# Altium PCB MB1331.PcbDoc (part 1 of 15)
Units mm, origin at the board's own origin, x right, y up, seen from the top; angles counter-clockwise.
Board outline 169.25 x 173.25 mm, 6 copper layers (Top Layer, Signal Layer 1, Signal Layer 2, Signal Layer 3, Signal Layer 4, Bottom Layer), stack 1.556 mm thick; 871 components, 699 nets, 3244 pads, 2370 vias.
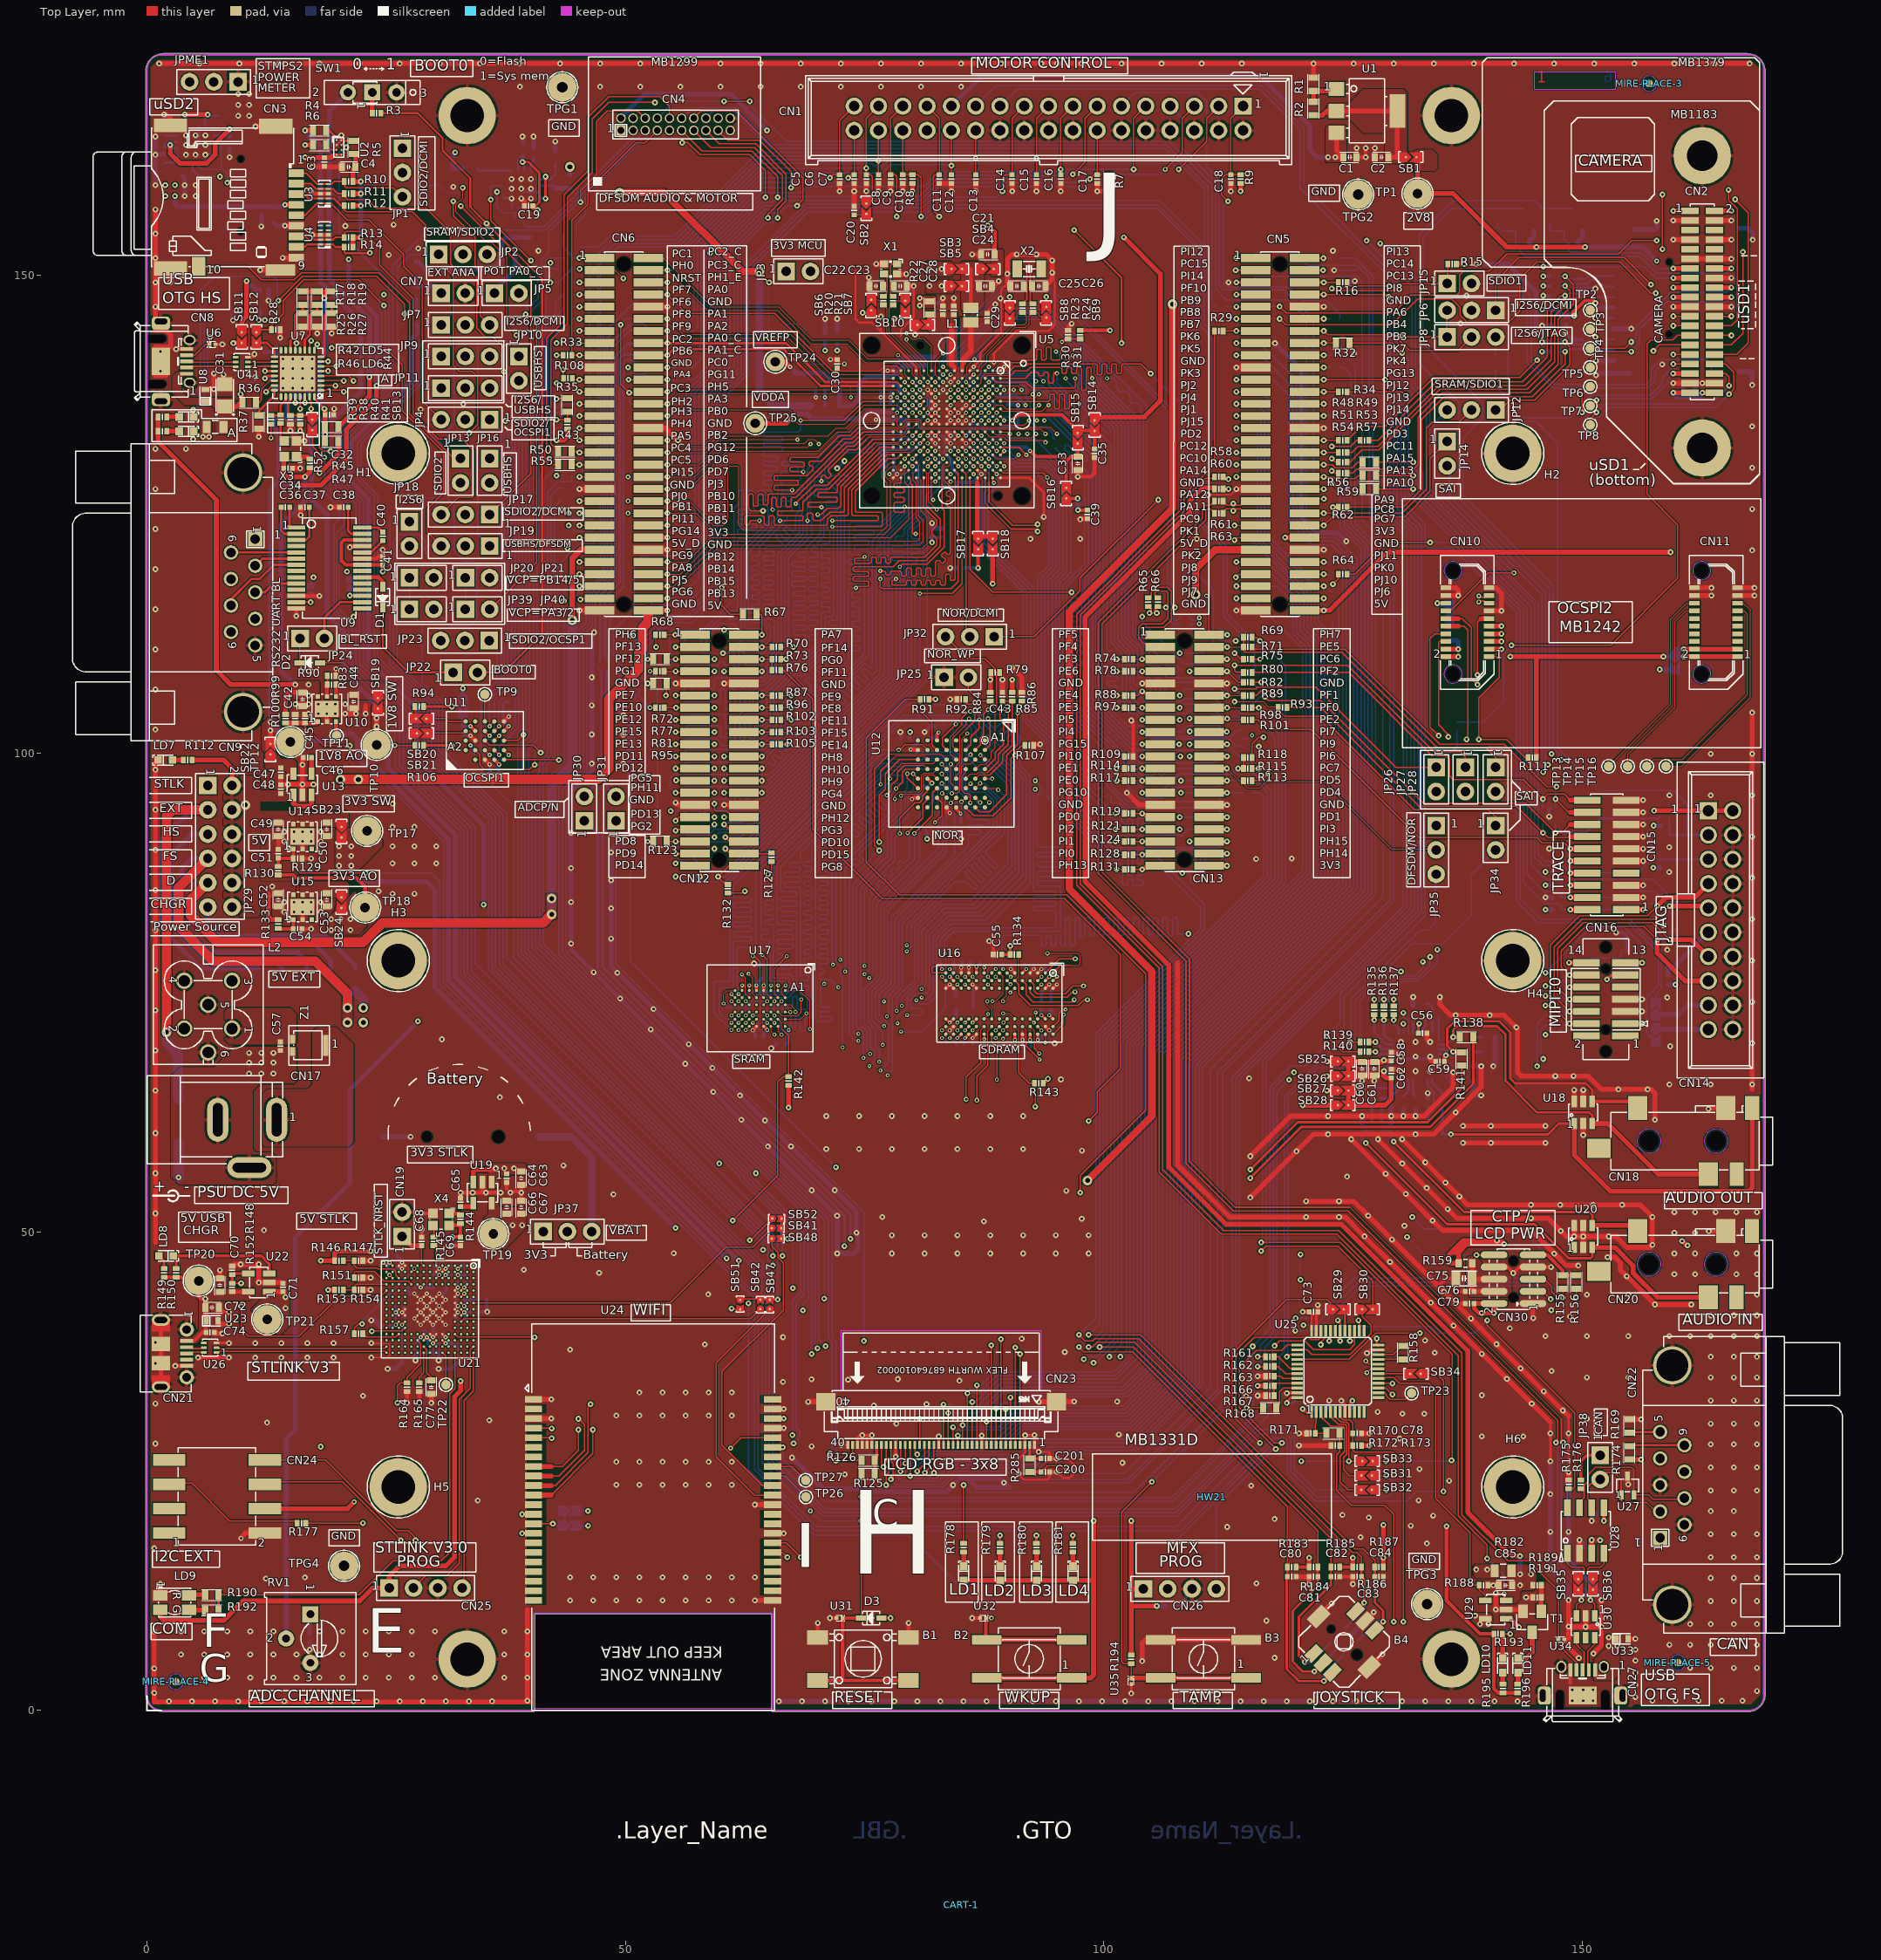
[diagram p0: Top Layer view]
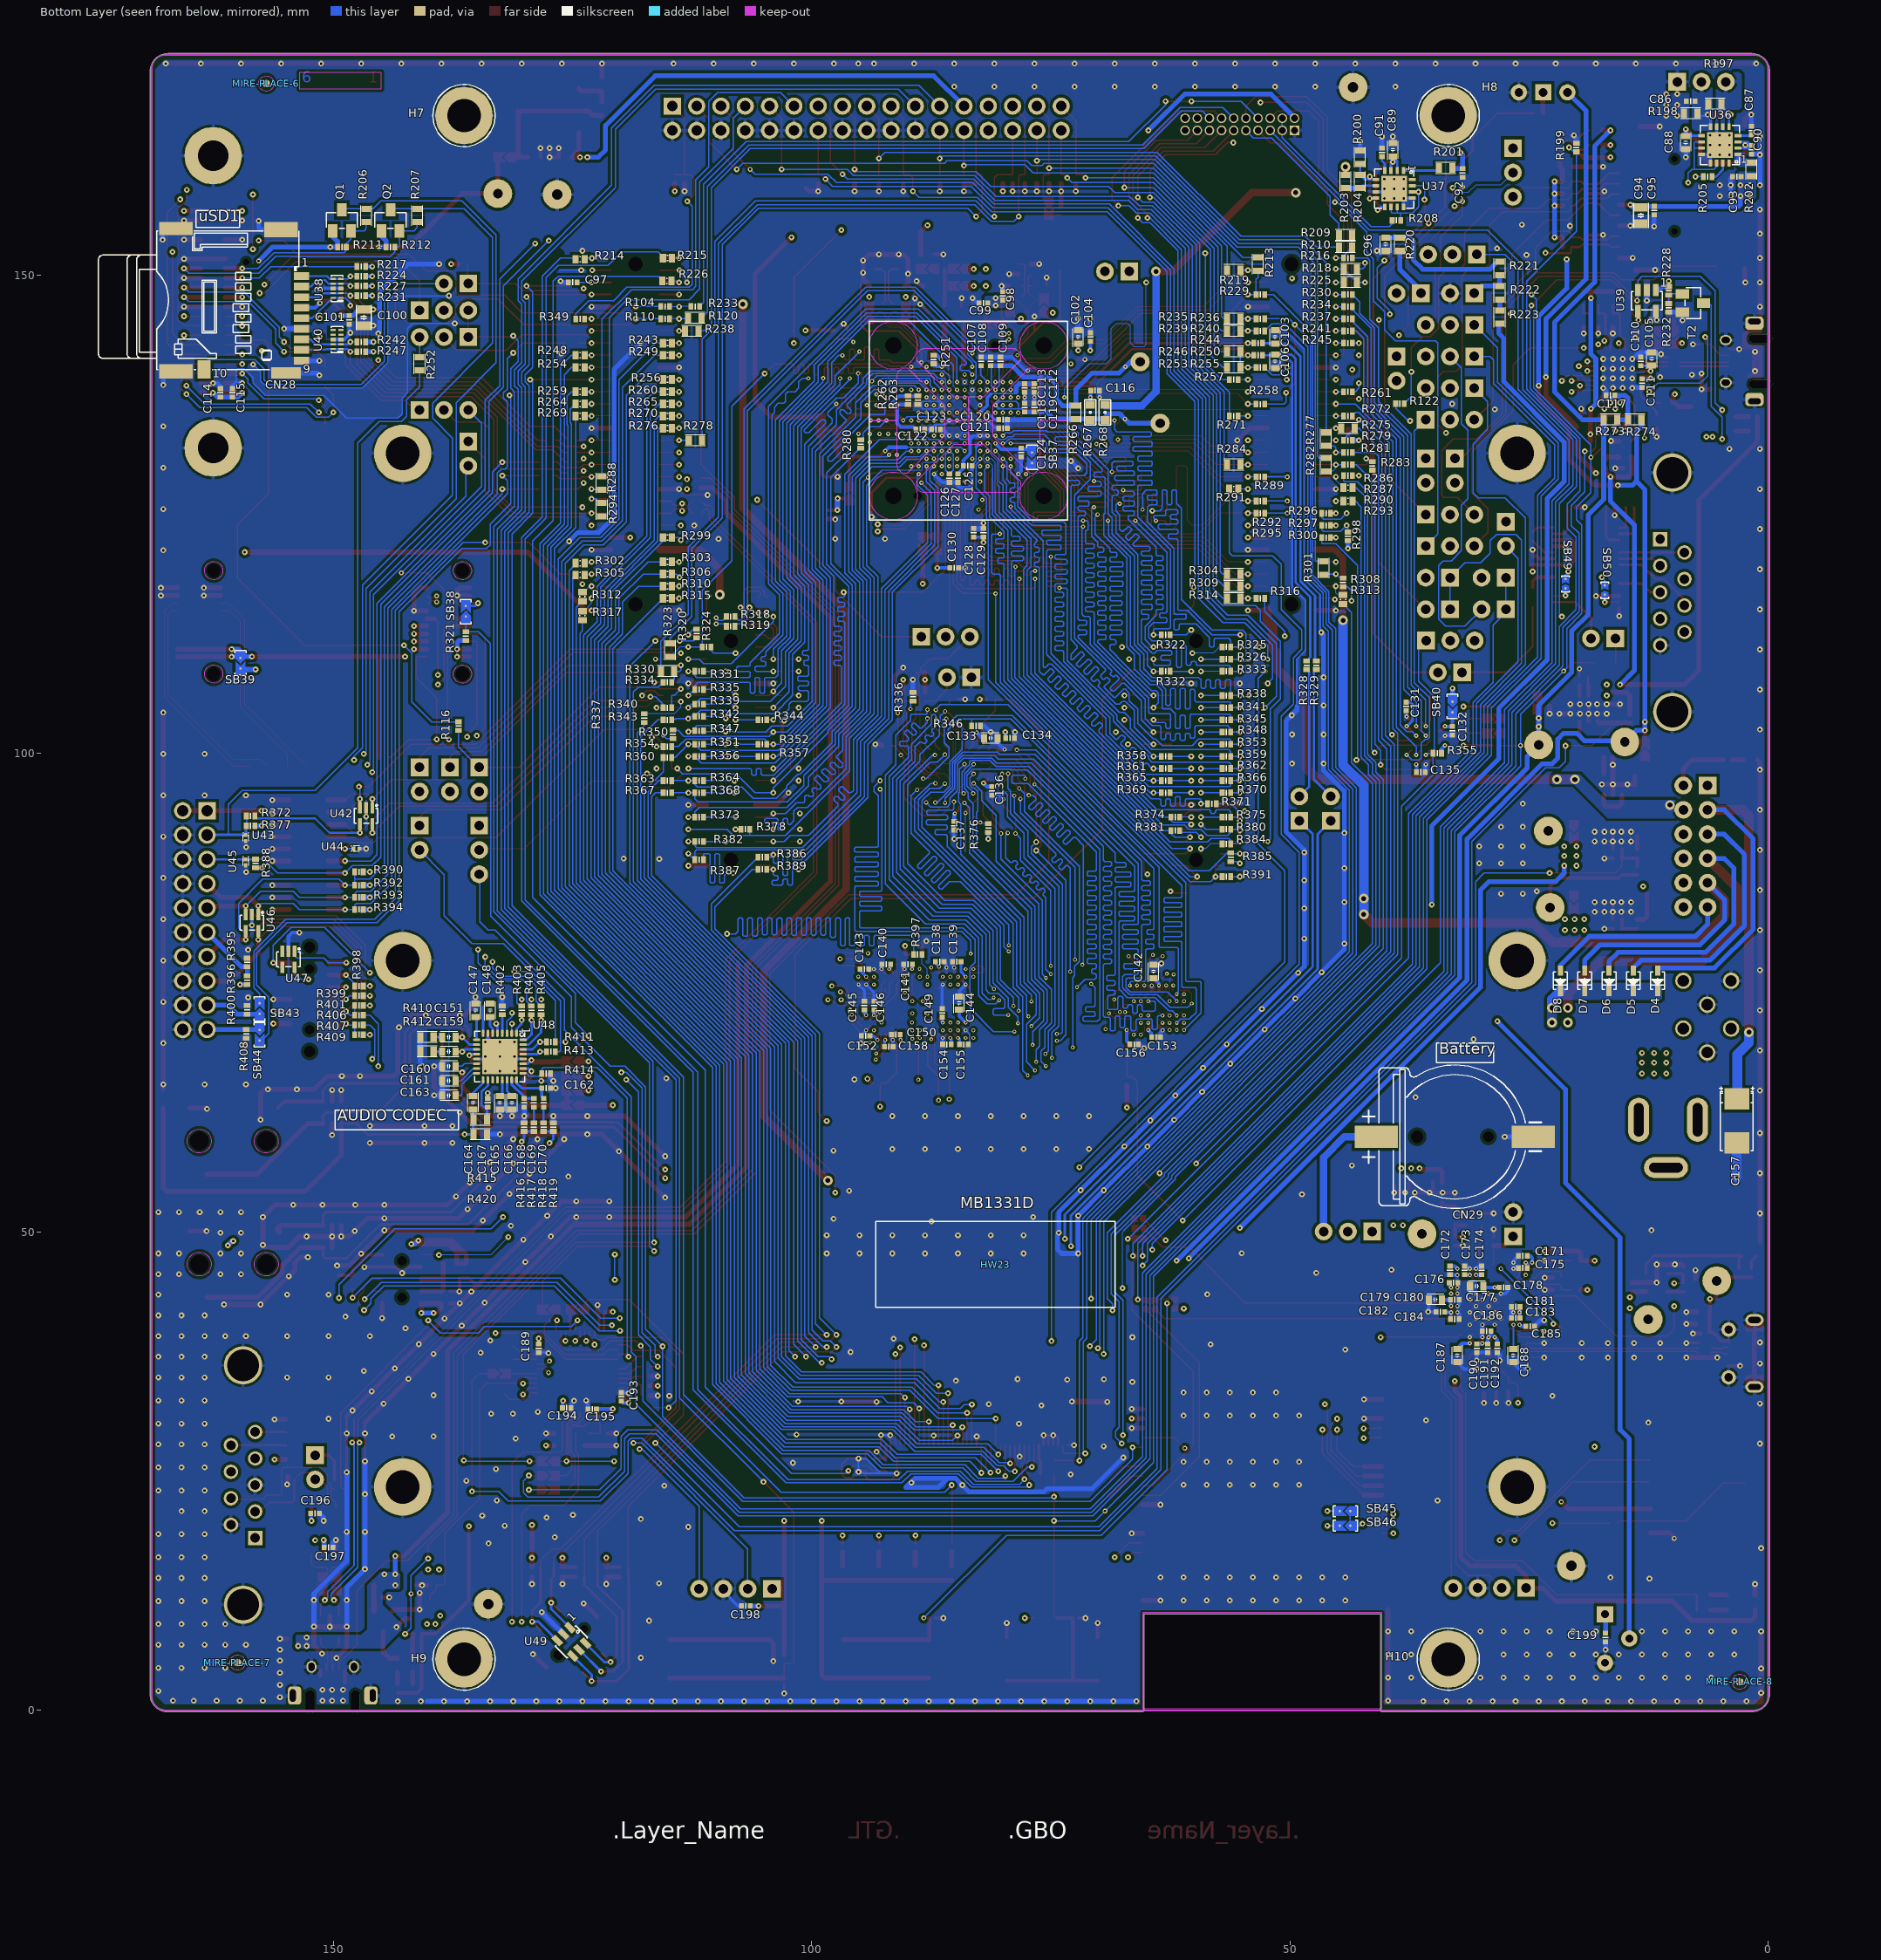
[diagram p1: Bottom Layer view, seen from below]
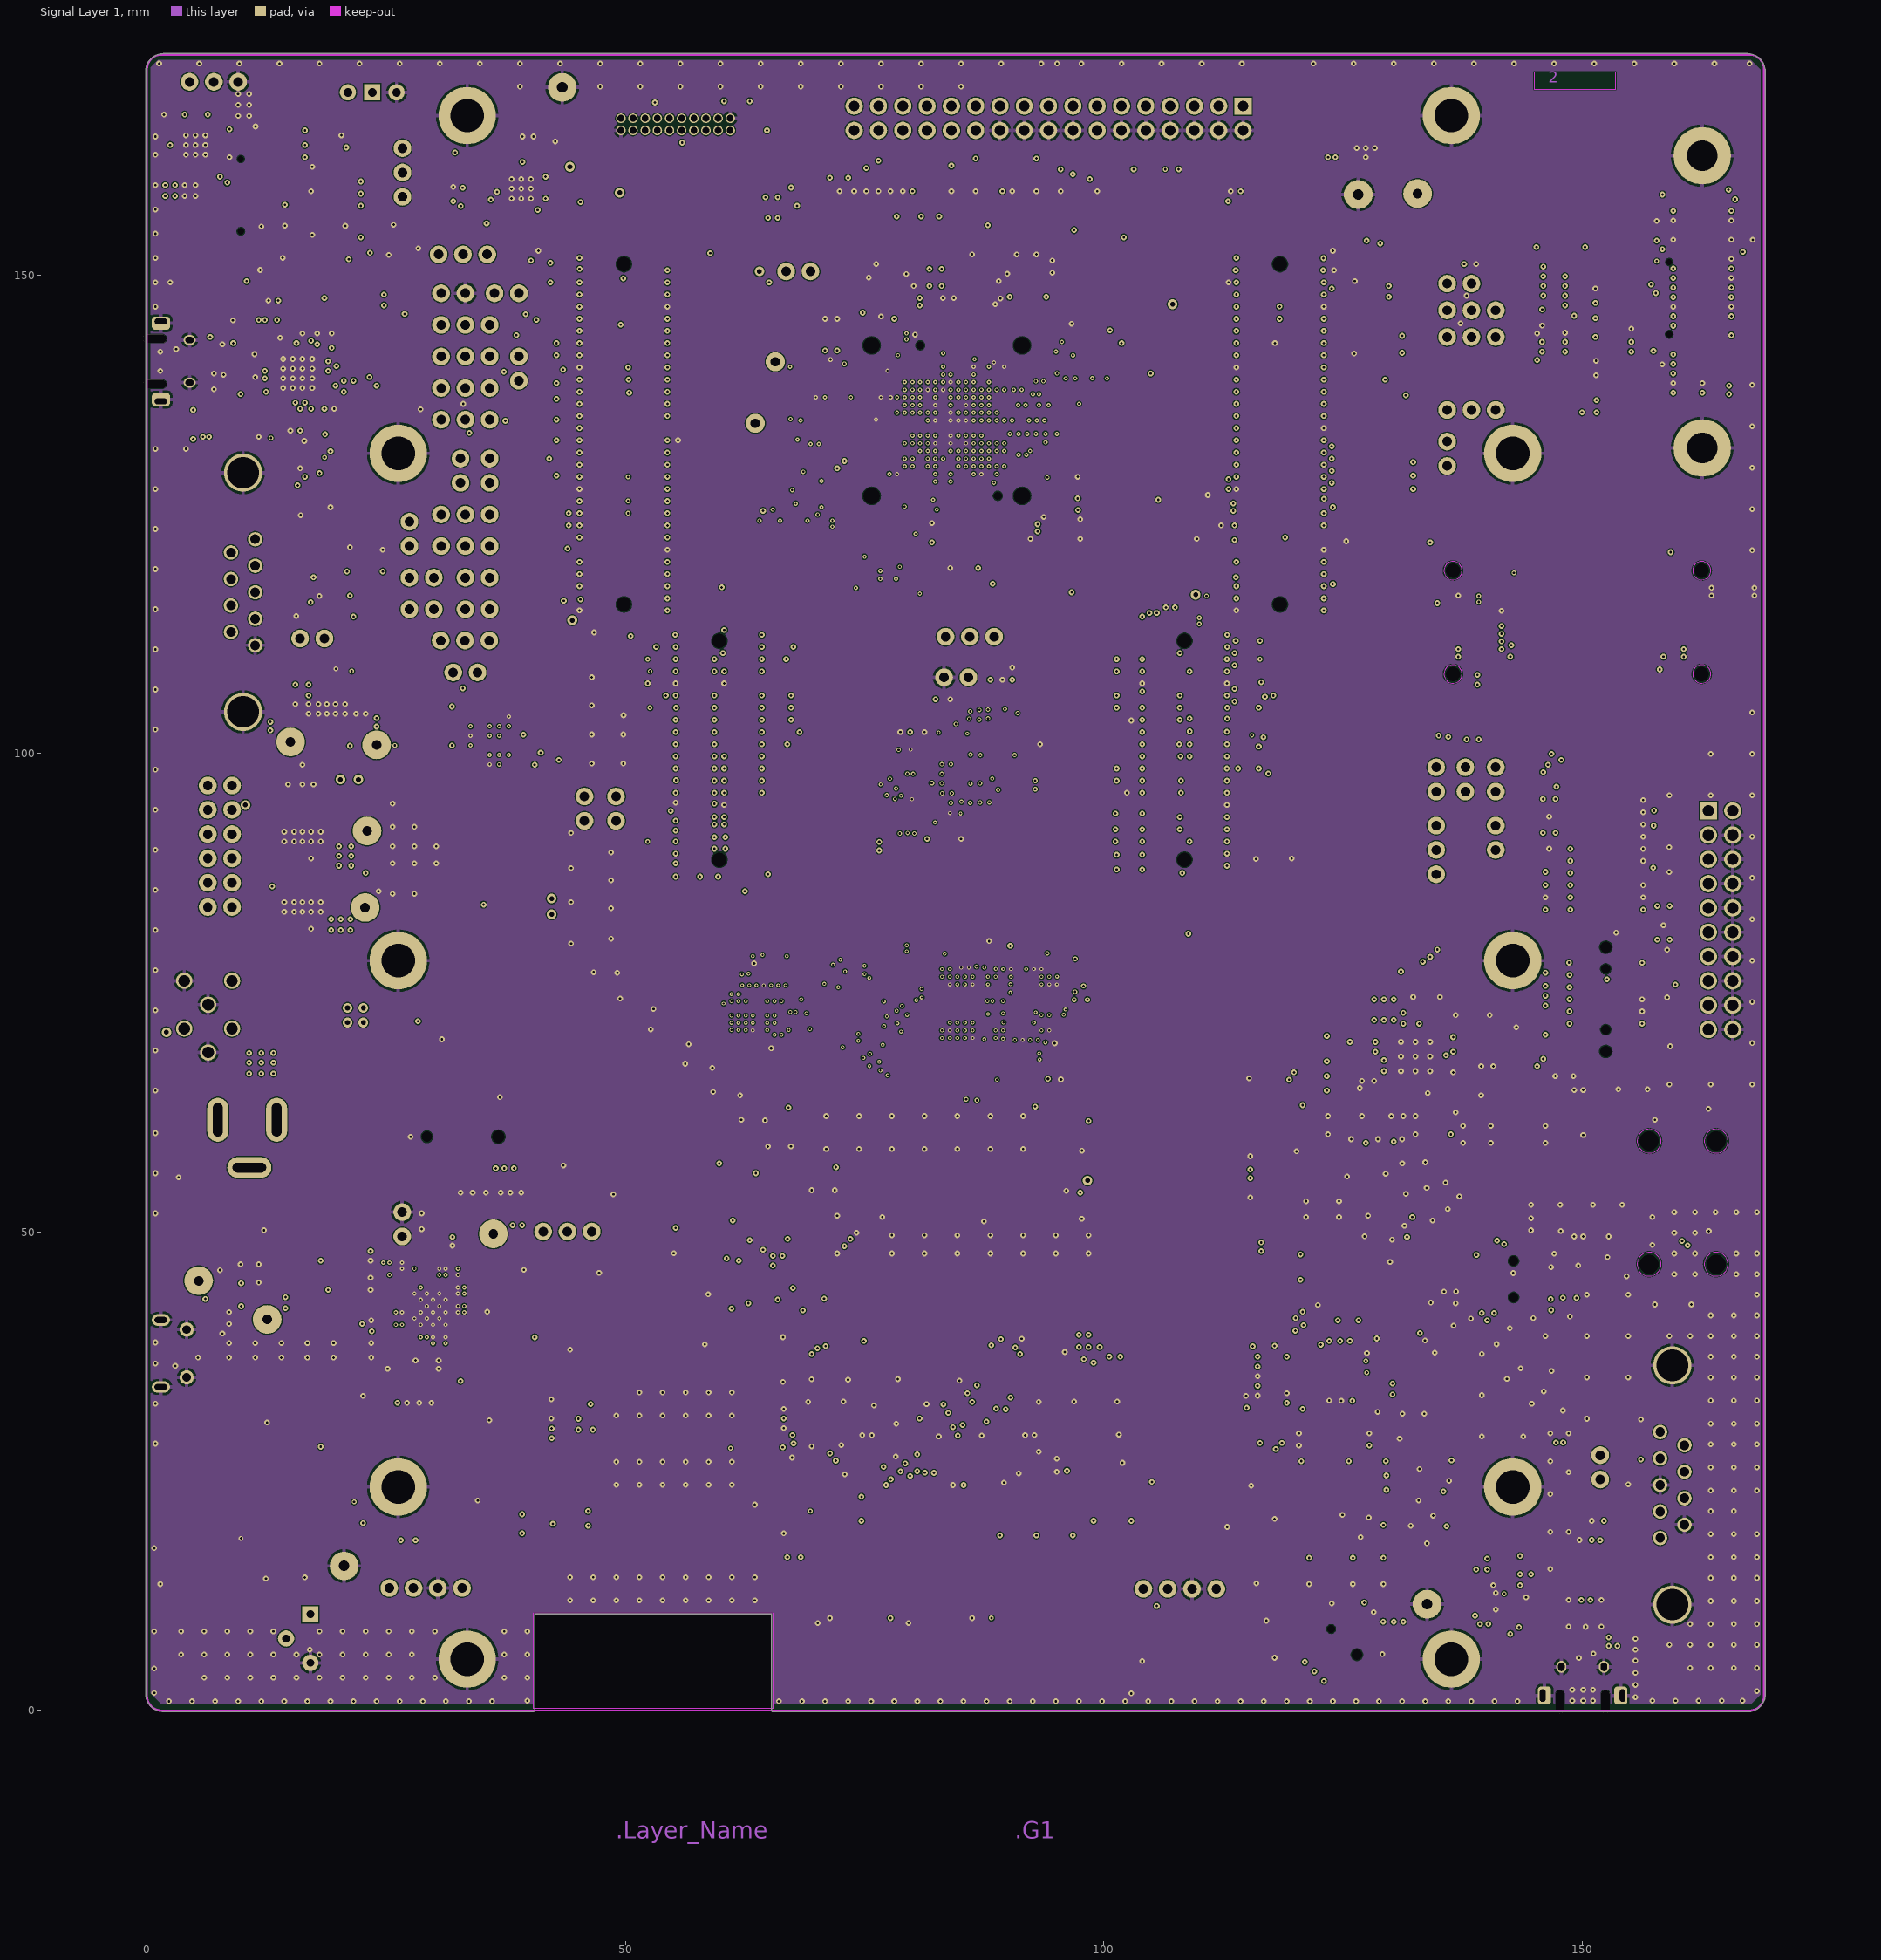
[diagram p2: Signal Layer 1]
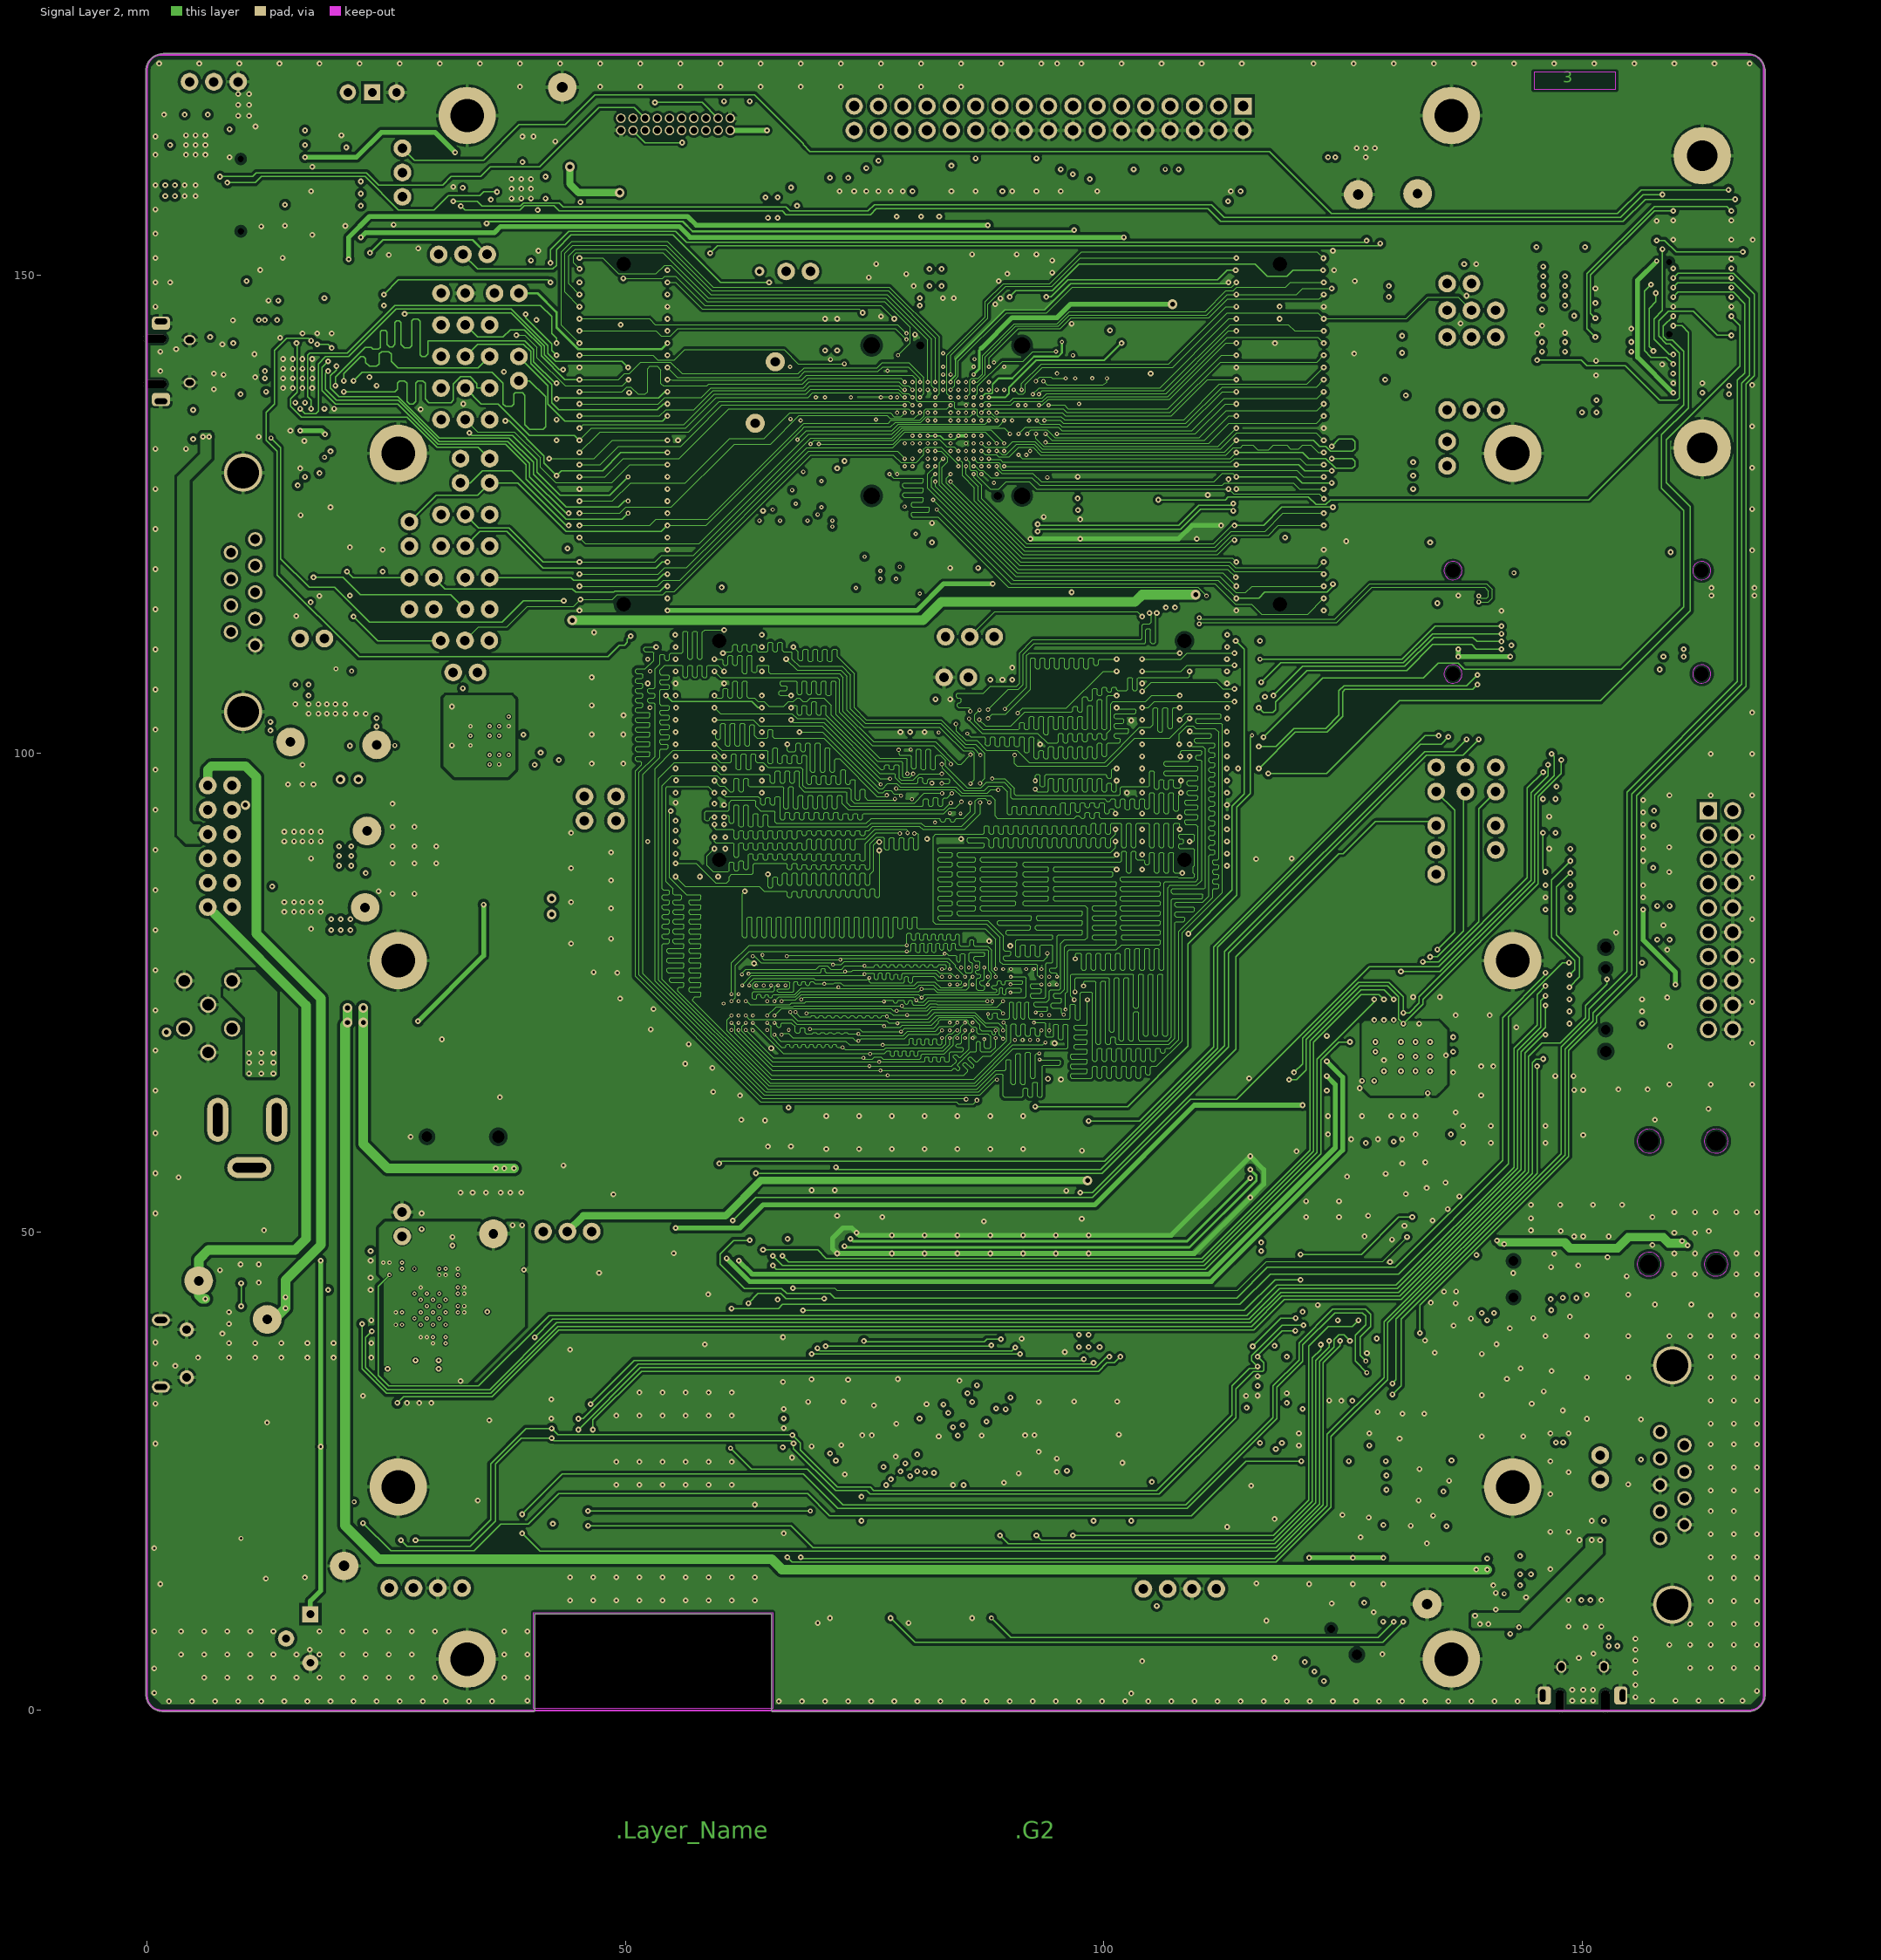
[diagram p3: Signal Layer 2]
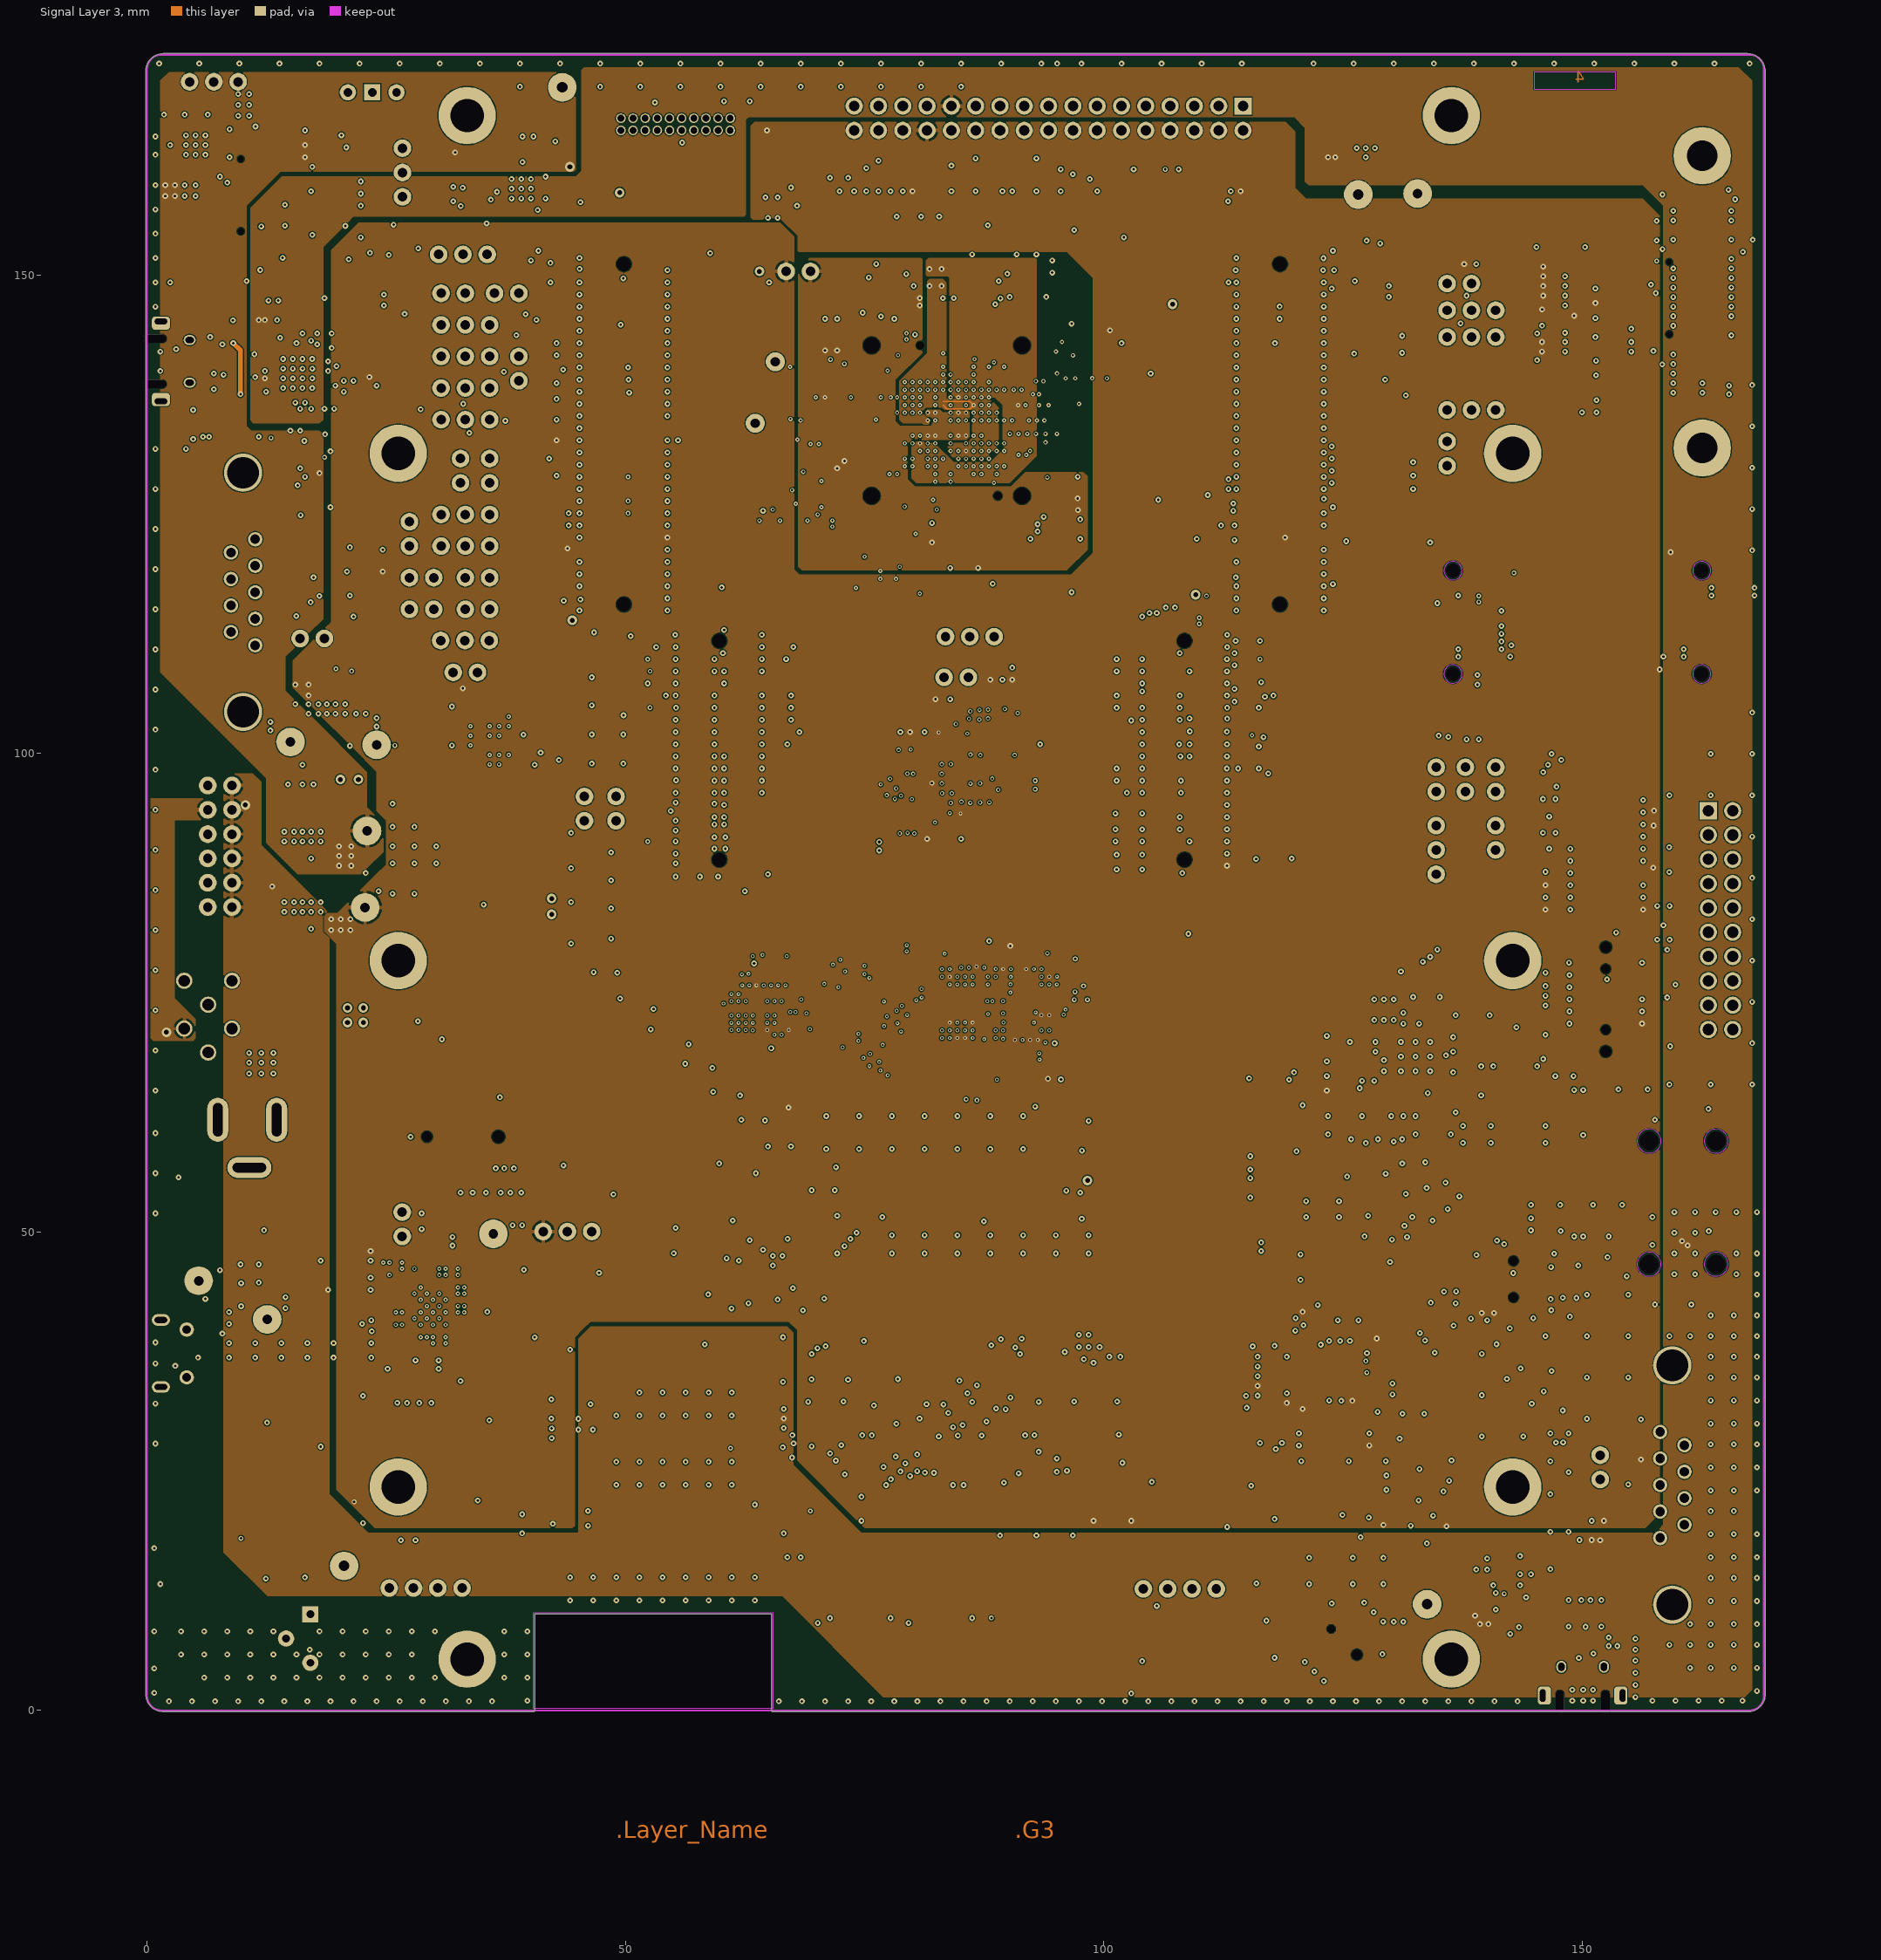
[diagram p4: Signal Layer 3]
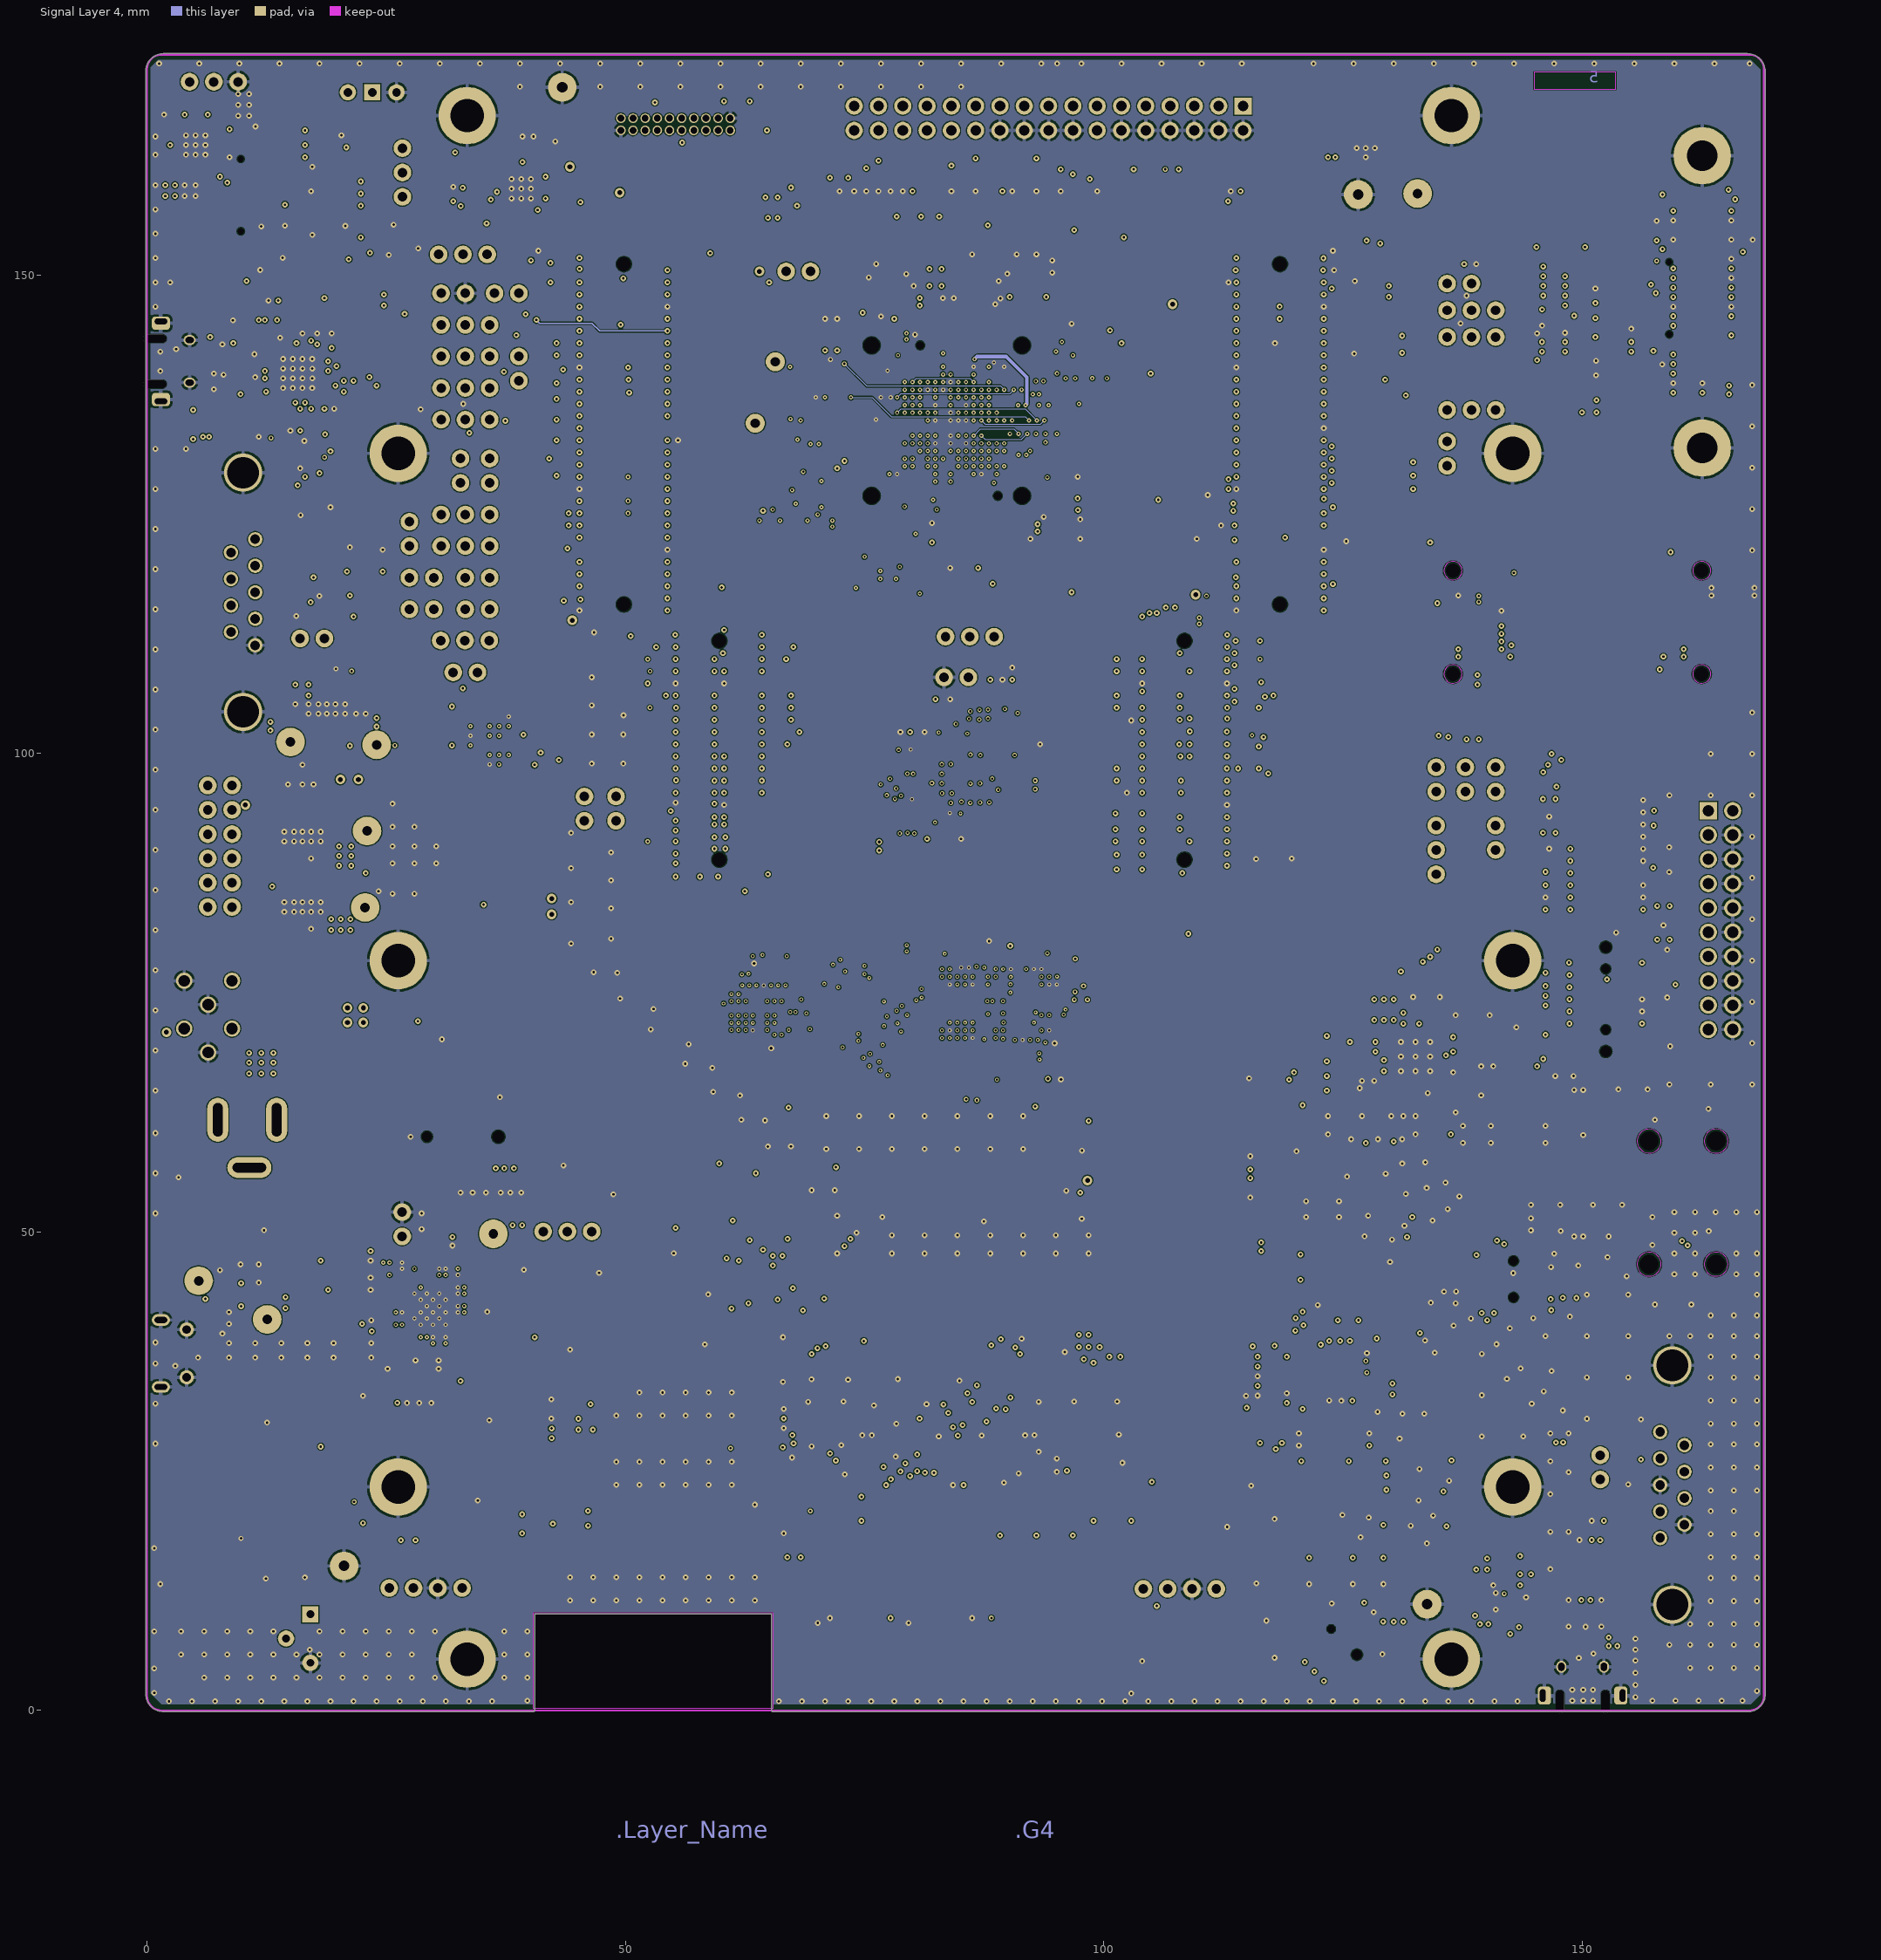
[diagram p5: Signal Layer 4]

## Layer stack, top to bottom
Top Solder: solder mask 0.0203, Solder Resist, Dk 3.5
Top Layer: signal copper 0.037
Dielectric 1: prepreg 0.0986, IT-180A 3313H, Dk 4.2
Signal Layer 1: signal copper 0.035
Dielectric 2: core 0.13, IT-180A, Dk 4.2
Signal Layer 2: signal copper 0.035
Dielectric 3: core 0.885, IT-180A 1080*2, Dk 4.25
Signal Layer 3: signal copper 0.035
Dielectric 4: core 0.13, IT-180A, Dk 4.2
Signal Layer 4: signal copper 0.035
Dielectric 5: prepreg 0.0986, IT-180A 3313H, Dk 4.2
Bottom Layer: signal copper 0.037
Bottom Solder: solder mask 0.0203, Solder Resist, Dk 3.5

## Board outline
-0.127,1.691 ccw(c1.725,1.725) 1.725,-0.127 ccw(c1.725,0) 1.725,-0.127 40.4,-0.117 ccw(c40.4,0.01) 40.527,0.01 40.527,10.073 65.273,10.073 65.273,0.01 ccw(c65.4,0.01) 65.4,-0.117 167.333,-0.127 ccw(c167.333,0) 167.333,-0.127 ccw(c167.333,1.667) 169.127,1.667 169.127,171.275 ccw(c167.275,171.275) 167.275,173.127 ccw(c167.275,173) 167.258,173.126 ccw(c167.24,173) 167.24,173.127 1.715,173.127 ccw(c1.715,173) 1.711,173.127 cw(c1.725,171.275) 1.725,173.127 1.711,173.127 ccw(c1.725,171.275) -0.127,171.275 ccw(c0,171.275) -0.127,171.262 ccw(c0,171.25) -0.127,171.25 -0.127,1.7 ccw(c0,1.7)

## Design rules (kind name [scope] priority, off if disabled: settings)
Clearance Clearance_4 [InNamedPolygon('GND_L03_P1184')] p1: gap=0.3 ignorepadtopadclearanceinfootprint=FALSE
Clearance Clearance_3 [InNamedPolygon('GND_L06_P1186')] p2: gap=0.3 ignorepadtopadclearanceinfootprint=FALSE
Clearance Clearance_2 [InNamedPolygon('GND_L01_P1178')] p3: gap=0.3 ignorepadtopadclearanceinfootprint=FALSE
Clearance Clearance_1 [All] p4 off: gap=0.1 ignorepadtopadclearanceinfootprint=TRUE except(0.15: Arc-Fill Track-Fill SMDPad-Fill THPad-Fill Via-Fill Fill-Fill; 0.2: Arc-THPad Track-THPad SMDPad-SMDPad SMDPad-THPad THPad-THPad; 0.3: Arc-Poly Track-Poly SMDPad-Poly THPad-Poly Via-Poly Poly-Poly)
Clearance [All] p5: gap=0.1 ignorepadtopadclearanceinfootprint=TRUE except(0.15: Arc-Fill Track-Fill SMDPad-Fill THPad-Fill Via-Fill Fill-Fill; 0.2: Arc-THPad Track-THPad SMDPad-SMDPad SMDPad-THPad THPad-THPad)
ComponentClearance [All] p1 off: gap=0.025 collisioncheckmode=3 verticalgap=0 showdistances=FALSE
DiffPairsRouting DiffPairsRouting_ADC_DIFF [InDifferentialPair('ADC_IN')   Or InDifferentialPair('ADC_JP_IN')    Or InDifferentialPair('ADC_JP_OUT')] p1: maxlimit=0.15 minlimit=0.15 mostfreqgap=0.15 toplayer_minwidth=0.254 toplayer_maxwidth=0.254 toplayer_prefwidth=0.254 midlayer1_minwidth=0.254 midlayer1_maxwidth=0.254 midlayer1_prefwidth=0.254 midlayer2_minwidth=0.254 midlayer2_maxwidth=0.254 midlayer2_prefwidth=0.254 midlayer3_minwidth=0.254 midlayer3_maxwidth=0.254 midlayer3_prefwidth=0.254 midlayer4_minwidth=0.254 midlayer4_maxwidth=0.254 midlayer4_prefwidth=0.254 bottomlayer_minwidth=0.254 bottomlayer_maxwidth=0.254 bottomlayer_prefwidth=0.254 maxuncoupledlength=12.7
DiffPairsRouting DiffPairsRouting_100 [InDifferentialPairClass('Diff_100')] p2: maxlimit=0.277 minlimit=0.251 mostfreqgap=0.277 toplayer_maxgap=0.251 toplayer_prefgap=0.251 toplayer_minwidth=0.13 toplayer_maxwidth=0.13 toplayer_prefwidth=0.13 midlayer1_mingap=0.277 midlayer1_minwidth=0.381 midlayer1_maxwidth=0.381 midlayer1_prefwidth=0.381 midlayer2_mingap=0.277 midlayer2_minwidth=0.104 midlayer2_maxwidth=0.104 midlayer2_prefwidth=0.104 midlayer3_mingap=0.277 midlayer3_minwidth=0.381 midlayer3_maxwidth=0.381 midlayer3_prefwidth=0.381 midlayer4_mingap=0.277 midlayer4_minwidth=0.381 midlayer4_maxwidth=0.381 midlayer4_prefwidth=0.381 bottomlayer_maxgap=0.251 bottomlayer_prefgap=0.251 bottomlayer_minwidth=0.13 bottomlayer_maxwidth=0.13 bottomlayer_prefwidth=0.13 maxuncoupledlength=12.7
DiffPairsRouting DiffPairsRouting_90 [InDifferentialPairClass('Diff_90')] p3: maxlimit=0.251 minlimit=0.226 mostfreqgap=0.251 toplayer_maxgap=0.226 toplayer_prefgap=0.226 toplayer_minwidth=0.155 toplayer_maxwidth=0.155 toplayer_prefwidth=0.155 midlayer1_mingap=0.251 midlayer1_minwidth=0.381 midlayer1_maxwidth=0.381 midlayer1_prefwidth=0.381 midlayer2_mingap=0.251 midlayer2_minwidth=0.13 midlayer2_maxwidth=0.13 midlayer2_prefwidth=0.13 midlayer3_mingap=0.251 midlayer3_minwidth=0.381 midlayer3_maxwidth=0.381 midlayer3_prefwidth=0.381 midlayer4_mingap=0.251 midlayer4_minwidth=0.381 midlayer4_maxwidth=0.381 midlayer4_prefwidth=0.381 bottomlayer_maxgap=0.226 bottomlayer_prefgap=0.226 bottomlayer_minwidth=0.155 bottomlayer_maxwidth=0.155 bottomlayer_prefwidth=0.155 maxuncoupledlength=12.7
FabricationTestpoint [(IsPad And (OnTopLayer Or OnBottomLayer))] p1: side=3 testpointundercomponent=TRUE minsize=1.016 maxsize=2.54 preferedsize=1.524 minholesize=0 maxholesize=1.016 preferedholesize=0.813 testpointgrid=0.025 allowsidetop=TRUE allowsidebottom=TRUE usegrid=TRUE gridtolerance=0
HoleSize [All] p1: absolutevalues=TRUE maxlimit=25.375 minlimit=0.025 maxpercent=80.000 minpercent=20.000
MatchedLengths MatchedLengths_SDIO1_MCU [InNetClass('SDIO1_MCU')] p1: tolerance=7 checknetsindiffpair=FALSE checkdiffpairvsdiffpair=TRUE checkxsignals=TRUE checkothers=TRUE
MatchedLengths MatchedLengths_SDIO2_MCU [InNetClass('SDIO2_MCU')] p2: tolerance=7 checknetsindiffpair=FALSE checkdiffpairvsdiffpair=TRUE checkxsignals=TRUE checkothers=TRUE
MatchedLengths MatchedLengths_ULPI_MCU [InNetClass('ULPI_MCU')] p3: tolerance=17 checknetsindiffpair=FALSE checkdiffpairvsdiffpair=TRUE checkxsignals=TRUE checkothers=TRUE
MatchedLengths MatchedLengths_CAMERA_MCU [InNetClass('CAMERA_MCU')] p4: tolerance=17 checknetsindiffpair=FALSE checkdiffpairvsdiffpair=TRUE checkxsignals=TRUE checkothers=TRUE
MatchedLengths MatchedLengths_FMC_DATA_MCU [InNetClass('FMC DATA_MCU')] p5: tolerance=3 checknetsindiffpair=FALSE checkdiffpairvsdiffpair=TRUE checkxsignals=TRUE checkothers=TRUE
MatchedLengths MatchedLengths_FMC_ADR_CMD_MCU [InNetClass('FMC ADR+CMD_MCU')] p6: tolerance=3 checknetsindiffpair=FALSE checkdiffpairvsdiffpair=TRUE checkxsignals=TRUE checkothers=TRUE
MatchedLengths MatchedLengths_SDIO1 [InNetClass('SDIO1')] p7: tolerance=7 checknetsindiffpair=FALSE checkdiffpairvsdiffpair=TRUE checkxsignals=TRUE checkothers=TRUE
MatchedLengths MatchedLengths_SDIO2 [InNetClass('SDIO2')] p8: tolerance=7 checknetsindiffpair=FALSE checkdiffpairvsdiffpair=TRUE checkxsignals=TRUE checkothers=TRUE
MatchedLengths MatchedLengths_ULPI [InNetClass('ULPI')] p9: tolerance=17 checknetsindiffpair=FALSE checkdiffpairvsdiffpair=TRUE checkxsignals=TRUE checkothers=TRUE
MatchedLengths MatchedLengths_CAMERA [InNetClass('CAMERA')] p10: tolerance=17 checknetsindiffpair=FALSE checkdiffpairvsdiffpair=TRUE checkxsignals=TRUE checkothers=TRUE
MatchedLengths MatchedLengths_FMC_DATA [InNetClass('FMC DATA')] p11: tolerance=3 checknetsindiffpair=FALSE checkdiffpairvsdiffpair=TRUE checkxsignals=TRUE checkothers=TRUE
MatchedLengths MatchedLengths_FMC_ADR_CMD [InNetClass('FMC ADR+CMD')] p12: tolerance=3 checknetsindiffpair=FALSE checkdiffpairvsdiffpair=TRUE checkxsignals=TRUE checkothers=TRUE
MaxMinImpedance "Schematic Impedance Constraint" [InNet('USB_DEV_HS_P')] p1: minimum=85,00 maximum=95,00
MaxMinImpedance "Schematic Impedance Constraint_6" [InNet('USB_DEV_HS_N')] p2: minimum=85,00 maximum=95,00
MaxMinImpedance "Schematic Impedance Constraint_3" [InNet('USB_DEV_HS_CN_P')] p3: minimum=85,00 maximum=95,00
MaxMinImpedance "Schematic Impedance Constraint_2" [InNet('USB_DEV_HS_CN_N')] p4: minimum=85,00 maximum=95,00
MinimumSolderMaskSliver [All] p1: minsoldermaskwidth=0
PlaneClearance [All] p1: clearance=0.6
PlaneConnect [All] p1: planeconnectstyle=Direct reliefexpansion=0.508 reliefentries=4 reliefconductorwidth=0.4 reliefairgap=0.4
PolygonConnect PolygonConnect_via [IsVia] p1: connectstyle=Direct reliefconductorwidth=0.254 reliefentries=4 polygonreliefangle="90 Angle" airgapwidth=0.254
PolygonConnect [All] p2: thpad.connectstyle=Relief thpad.reliefconductorwidth=0.4 thpad.reliefentries=4 thpad.polygonreliefangle="90 Angle" thpad.airgapwidth=0.25 smdpad.connectstyle=Direct smdpad.reliefconductorwidth=0.4 smdpad.reliefentries=4 smdpad.polygonreliefangle="90 Angle" smdpad.airgapwidth=0.254 via.connectstyle=Direct via.reliefconductorwidth=0.4 via.reliefentries=4 via.polygonreliefangle="90 Angle" via.airgapwidth=0.254
RoutingPriority RoutingPriority_ALL [All] p1: routingpriority=1
RoutingVias [All] p1: holewidth=0.254 width=0.6 viastyle="Through Hole" minholewidth=0.254 minwidth=0.6 maxholewidth=0.254 maxwidth=0.6
SilkToSilkClearance [All] p1: silktosilkclearance=0
SilkToSolderMaskClearance [IsPad] p1: minsilkscreentomaskgap=0 clearancetoexposedcopper=TRUE
SolderMaskExpansion [All] p1: expansion=0.05
Width Width_POWER [InNetClass('Power')] p1: maxlimit=2 minlimit=0.1 preferedwidth=0.4 minimp=50.000000 maximp=50.000000 favimp=50.000000
Width [All] p2: maxlimit=253.975 minlimit=0.1 preferedwidth=0.1
20 further rules are at their usual default settings.

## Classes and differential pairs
net class "UART VCP": J_RX J_TX PA2 PA3 PB14 PB15 RS232_USART_RX RS232_USART_TX STLK_VCP_RX STLK_VCP_TX T_VCP_RX T_VCP_TX WIFI_UART_RX WIFI_UART_TX
differential pair class ADC_DIFF: ADC_IN ADC_JP_IN ADC_JP_OUT
net class "USB FS_MCU": PA11 PA12
net class ULPI: ULPI_D0 ULPI_D1 ULPI_D2 ULPI_D3 ULPI_D4 ULPI_D5 ULPI_D6 ULPI_D7
net class SDIO2_MCU: PG0 PG1 PG2 PG3 PG4 PG5 PG6 PG7 PG8 PG9 PG10 PG11 PG12 PG13 PG14 PG15
net class SDIO1_MCU: PC0 PC1 PC2 PC3 PC4 PC5 PC6 PC7 PC8 PC9 PC10 PC11 PC12 PC13 PC14 PC15
net class "SDR DATA": D0 D1 D2 D3 D4 D5 D6 D7 D8 D9 D10 D11 D12 D13 D14 D15 D16 D17 D18 D19 D20 D21 D22 D23 D24 D25 D26 D27 D28 D29 D30 D31
net class "SDR ADR+CMD": A0 A1 A2 A3 A4 A5 A6 A7 A8 A9 A10 A11 A12 A13 A14 A15 A16 A17 A18 A19 A20 A21 A22 A23
net class CAMERA: DCMI_D0 DCMI_D1 DCMI_D2 DCMI_D3 DCMI_D4 DCMI_D5 DCMI_D6 DCMI_D7
net class SDIO2: SDIO2_CK SDIO2_CMD SDIO2_D0 SDIO2_D1 SDIO2_D2 SDIO2_D3
net class SDIO1: SDIO1_CK SDIO1_CMD SDIO1_D0 SDIO1_D1 SDIO1_D2 SDIO1_D3
net class "USB HS USER": USB_HS_N USB_HS_P
net class "USB FS": USB_OTG_FS_N USB_OTG_FS_P
net class "USB HS STLINK": USB_DEV_HS_CN_N USB_DEV_HS_CN_P USB_DEV_HS_N USB_DEV_HS_P
differential pair class Diff_90: USB_DEV_HS USB_DEV_HS_CN USB_HS USB_OTG_FS
differential pair class Diff_100: OCSPI2_CLK
net class ULPI_MCU: PB0 PB1 PB2 PB3 PB4 PB5 PB6 PB7 PB8 PB9 PB10 PB11 PB12 PB13 PB14 PB15
net class CAMERA_MCU: PH0 PH1 PH2 PH3 PH4 PH5 PH6 PH7 PH8 PH9 PH10 PH11 PH12 PH13 PH14 PH15
net class "SDR DATA_MCU": PE0 PE1 PE2 PE3 PE4 PE5 PE6 PE7 PE8 PE9 PE10 PE11 PE12 PE13 PE14 PE15
net class "SDR ADR+CMD_MCU": PF0 PF1 PF2 PF3 PF4 PF5 PF6 PF7 PF8 PF9 PF10 PF11 PF12 PF13 PF14 PF15
component class U_USB_OTG_HS_externalPHY: C31 C32 C34 C105 C110 C111 C117 CN8 LD5 LD6 R17 R18 R19 R25 R26 R27 R28 R36 R37 R38 R39 R40 R41 R42 R44 R45 R46 R47 R52 R228 R232 R273 R274 SB11 SB12 SB13 T2 U6 U7 U8 U39 U41 X3
component class U_USB_OTG_FS: C85 CN27 LD10 LD11 R182 R188 R189 R191 R193 R195 R196 T1 U29 U30 U33 U34
component class U_Top: H7 H8 H9 H10 HW8 HW9 HW10 HW11 HW12 HW13 HW14 HW15 HW16 HW17 HW18 HW19 HW20 HW21 HW22 HW23 HW24 HW25 HW26 SB29 SB30 SB31 SB32 SB33 SB34 TPG1 TPG2 TPG3 TPG4
component class U_STMPS2&PT100: C19 C86 C87 C88 C89 C90 C91 C92 C93 JPME1 R33 R197 R198 R200 R201 R202 R203 R204 R205 R208 U36 U37
component class U_STLink_V3E_SWD: C63 C64 C65 C66 C67 C68 C69 C70 C71 C72 C74 C77 C171 C172 C173 C174 C175 C176 C177 C178 C179 C180 C181 C182 C183 C184 C185 C186 C187 C188 C190 C191 C192 CN19 CN21 CN25 D4 D5 D6 D7 D8 LD8 LD9 R144 R145 R146 R147 R148 R149 R150 R151 R152 R153 R154 R157 R165 R190 R192 R398 R399 R401 R409 SB41 SB42 TP19 TP20 TP21 TP22 U19 U21 U22 U23 U26 X4
component class U_SDcard: C94 C95 C100 C101 CN3 CN28 HW46 HW47 JP13 JP15 R10 R11 R12 R13 R14 R15 R224 R227 R231 R242 R247 R298 U3 U4 U38 U40
component class U_Power_MCU: C21 C24 C27 C28 C29 C33 C35 C39 C98 C99 C102 C104 C108 C109 C112 C113 C116 C118 C119 C120 C121 C122 C123 C124 C125 C126 C127 C128 C129 C130 CN29 HW56 HW57 JP3 JP37 L1 R22 R251 R262 R263 R266 R267 R268 SB3 SB4 SB5 SB10 SB14 SB15 SB16 SB17 SB18 SB37 SB73 TP24 TP25
component class U_Power_Board: C1 C2 C42 C44 C45 C46 C47 C48 C49 C50 C51 C52 C53 C54 C57 C157 CN17 HW55 JP29 L2 LD7 R1 R2 R83 R90 R99 R100 R112 R129 R130 R133 SB1 SB19 SB22 SB23 SB24 TP1 TP10 TP11 TP12 TP17 TP18 U1 U10 U13 U14 U15 Z1
component class U_Peripherals: B2 B3 C96 C199 CN7 CN24 HW51 HW52 LD1 LD2 LD3 LD4 R172 R177 R178 R179 R180 R181 R194 R220 R221 R222 R223 R406 R407 RV1 SB45 SB46 TP26 TP27 U24 U32 U35
component class U_OCSPI: C131 C132 C135 CN10 CN11 HW45 R94 R106 R111 R321 R355 SB20 SB21 SB38 SB39 SB40 TP9 TP13 TP14 TP15 TP16 U11
component class U_MotorControl: B4 C5 C6 C7 C8 C9 C10 C11 C12 C13 C14 C15 C16 C17 C18 C20 C80 C81 C82 C83 C84 CN1 R7 R8 R9 R183 R184 R185 R186 R187 SB2 U49
component class U_MFX: C73 C78 C189 C193 C194 C195 C198 CN26 D3 R158 R161 R162 R163 R166 R167 R168 R170 R171 R173 TP23 U25
component class U_Memory: C43 C55 C133 C134 C136 C137 C138 C139 C140 C141 C142 C143 C144 C145 C146 C149 C150 C152 C153 C154 C155 C156 C158 JP25 R79 R84 R85 R86 R91 R92 R107 R109 R134 R142 R143 R336 R346 R376 R397 U12 U16 U17
component class U_MCU: 1.4 C30 C97 HW27 HW28 HW31 HW32 HW34 HW35 HW36 HW37 HW38 HW39 HW41 HW42 HW43 HW44 JP1 JP2 JP4 JP5 JP6 JP7 JP8 JP9 JP10 JP11 JP12 JP14 JP16 JP17 JP18 JP19 JP20 JP21 JP23 JP26 JP27 JP28 JP32 JP34 JP35 JP39 JP40 R16 R23 R24 R29 R34 R35 R43 R48 R49 R50 R51 R54 R55 R56 R58 R60 R61 R62 R63 R64 R65 R66 R67 R68 R69 R70 R71 R72 R73 R74 R75 R76 R77 R78 R80 R81 R82 R87 R88 R89 R93 R95 R96 R97 R98 R101 R102 R103 R104 R105 R108 R110 R113 R114 R115 R116 R117 R118 R119 R120 R121 R122 R123 R124 R127 R128 R131 R132 R209 R210 R213 R214 R215 R216 R219 R226 R229 R230 R233 R234 R235 R236 R237 R238 R239 R240 R241 R243 R244 R245 R246 R248 R249 R250 R253 R254 R255 R256 R257 R258 R259 R260 R261 R264 R265 R269 R270 R271 R272 R275 R276 R277 R278 R279 R280 R281 R282 R283 R284 R286 R287 R288 R289 R290 R291 R292 R293 R294 R295 R296 R297 R299 R300 R301 R302 R303 R304 R305 R306 R308 R309 R310 R312 R313 R314 R315 R316 R317 R318 R319 R320 R322 R323 R324 R325 R326 R330 R331 R332 R333 R334 R335 R337 R338 R339 R340 R341 R342 R343 R344 R345 R347 R348 R349 R350 R351 R352 R353 R354 R356 R357 R358 R359 R360 R361 R362 R363 R364 R365 R366 R367 R368 R369 R370 R371 R373 R374 R375 R378 R380 R381 R382 R384 R385 R386 R387 R389 R391 SB35 SB36 SB47 SB48 SB49 SB50 U5
component class U_MCU_Clock&Reset: B1 C22 C23 C25 C26 C107 D1 D2 JP22 JP24 R3 R20 R21 R30 R31 SW1 U31 X1 X2
component class U_LCD: C75 C76 C79 H1 H2 H3 H4 H5 H6 R159
component class U_JTAG&Trace: CN14 CN15 CN16 R32 R53 R57 R59 R164 R218 R252 R372 R377 R388 R390 R392 R393 R394 R395 R396 R400 R408 SB43 SB44 SB51 SB52 U42 U43 U44 U45 U46 U47
component class U_FDCAN&RS232: C36 C37 C38 C40 C41 C196 C197 CN9 CN22 HW53 HW54 JP38 R169 R174 R175 R176 U9 U27 U28
component class U_ExtensionConnector: CN5 CN6 CN12 CN13 R225 SB6 SB7 SB8 SB9
component class U_Camera: C114 C115 CN2 Q1 Q2 R206 R207 R211 R212 R217 TP2 TP3 TP4 TP5 TP6 TP7 TP8
component class U_DFSDM_Audio&Motor: CN4 HW48
component class U_Audio_Codec: C56 C58 C59 C60 C61 C62 C103 C106 C147 C148 C151 C159 C160 C161 C162 C163 C164 C165 C166 C167 C168 C169 C170 CN18 CN20 JP30 JP31 R135 R136 R137 R138 R139 R140 R141 R328 R329 R402 R403 R404 R405 R410 R411 R412 R413 R414 R415 R416 R417 R418 R419 R420 SB25 SB26 SB27 SB28 U18 U20 U48
net class Power: 1V8_AO 1V8_CODEC 1V8_LDO 1V8_SW 1V8_USBHS 2V8 3V3_AO 3V3_CODEC 3V3_MCU 3V3_OCSPI1 3V3_OCSPI2 3V3_SMPS_IN 3V3_STLK 3V3_SW 3V3_USBHS_IO 3V3_VBAT 3V3_VDDA 3V3_VREFP 5V 5V_D 5V_EXT 5V_EXT_CONN 5V_EXT_UNFILT 5V_STLK 5V_STLK_LDO_IN 5V_USB_CHGR 5V_USB_FS 5V_USB_HS GND GND_EXT_UNFILT VCAP VDD50_USB VDD_IO_MMC VDD_LDO VDD_MMC VDD_SMPS_IND_OUT VDD_SMPS_OUT VREGOUT33
differential pair ADC_JP_IN: +ADC_JP_OUT_P -ADC_JP_OUT_N
differential pair ADC_IN: +ADC_IN_P -ADC_IN_N
differential pair OCSPI2_CLK: +OCSPI2_CLK_P -OCSPI2_CLK_N
differential pair USB_HS: +USB_HS_P -USB_HS_N
differential pair USB_DEV_HS: +USB_DEV_HS_P -USB_DEV_HS_N
differential pair USB_DEV_HS_CN: +USB_DEV_HS_CN_P -USB_DEV_HS_CN_N
differential pair USB_OTG_FS: +USB_OTG_FS_P -USB_OTG_FS_N
differential pair ADC_JP_OUT: +ADC_JP_OUT_P -ADC_JP_OUT_N
differential pair ADC_JP_IN: +ADC_JP_IN_P -ADC_JP_IN_N

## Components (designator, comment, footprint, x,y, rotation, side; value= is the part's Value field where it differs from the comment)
B1 "SW-PUSH-CMS" SWI_WEALTHMETAL_TD-0341_4P_BLACK 74.843,5.387 r270 top locked value=SWITCH
B2 "SW_BLUE_KSC721GLFS" SWI_C&K_KSC721GLFS_BLUE 92.203,5.39 r180 top locked value=KSC721GLFS
B3 "SW_BLUE_KSC721GLFS" SWI_C&K_KSC721GLFS_BLUE 110.418,5.39 r180 top locked value=KSC721GLFS
B4 "Joystick MT-008A_M" SWI_XIEJIA_MT-008A_6P 125.111,7.166 r45 top locked value=MT-008A
C1 "Capacitor" C0603 125.73,162.306 r180 top value=10uF
C2 "Capacitor" C0603 129.032,162.306 r0 top value=10uF
C3 "Capacitor" C0402 18.542,161.798 r270 top value=100nF
C4 "Capacitor" C0603 21.082,161.29 r0 top value=1uF
C5 "Capacitor" C0402 72.39,160.02 r90 top value=100nF
C6 "Capacitor" C0402 73.914,160.02 r90 top value=100nF
C7 "Capacitor" C0402 75.184,160.02 r90 top value=100nF
C8 "Capacitor" C0402 76.454,160.02 r90 top value=100nF
C9 "Capacitor" C0402 77.724,160.02 r90 top value=100nF
C10 "Capacitor" C0402 78.994,160.02 r90 top value=1nF
C11 "Capacitor" C0402 82.804,160.02 r90 top value=100nF
C12 "Capacitor" C0402 84.074,160.02 r90 top value=100nF
C13 "Capacitor" C0402 86.614,160.02 r90 top value=100nF
C14 "Capacitor" C0402 90.424,160.02 r90 top value=100nF
C15 "Capacitor" C0402 92.964,160.02 r90 top value=100nF
C16 "Capacitor" C0402 95.504,160.02 r90 top value=100nF
C17 "Capacitor" C0402 99.314,160.02 r90 top value=100nF
C18 "Capacitor" C0402 113.284,160.02 r90 top value=1nF
C19 "Capacitor" C0402 39.878,157.226 r0 top value=1uF
C20 "Capacitor" C0402 73.914,156.718 r270 top value=10nF
C21 "Capacitor" C0603 87.884,152.146 r0 top value=4.7uF
C22 "Capacitor" C0603 76.2,148.844 r0 top value=2.7pF
C23 "Capacitor" C0603 78.74,148.844 r180 top value=2.7pF
C24 "Capacitor" C0603 87.63,148.844 r180 top value=10uF
C25 "Capacitor" C0603 90.932,148.844 r0 top value=2.7pF
C26 "Capacitor" C0603 93.218,148.844 r180 top value=2.7pF
C27 "Capacitor" C0402 83.185,146.304 r270 top value=10uF
C28 "Capacitor" C0402 84.328,146.304 r270 top value=10uF
C29 "Capacitor" C0402 87.8,145.55 r270 top value=100pF
C30 "Capacitor" C0402 72.136,140.716 r90 top value=100nF
C31 "Cap_POL_TANA" CPOL_TAJ-A_1206_H180 8.128,137.414 r90 top value="4.7uF 16V"
C32 "Capacitor" C0402 19.05,135.382 r180 top value=100nF
C33 "Capacitor" C0603 97.282,130.302 r270 top value=1uF
C34 "Capacitor" C0402 14.732,129.794 r180 top value=100nF
C35 "Capacitor" C0402 99.05,131.375 r270 top value=100nF
C36 "Capacitor" C0402 14.478,125.73 r180 top value=100nF
C37 "Capacitor" C0402 16.51,125.73 r0 top value=100nF
C38 "Capacitor" C0402 20.574,125.73 r0 top value=100nF
C39 "Capacitor" C0402 98.298,124.968 r270 top value=100nF
C40 "Capacitor" C0402 24.638,122.682 r90 top value=100nF
C41 "Capacitor" C0402 24.638,120.142 r90 top value=100nF
C42 "Capacitor" C0603 16.256,105.664 r270 top value=4.7uF
C43 "Capacitor" C0402 89.408,105.918 r90 top value=100nF
C44 "Capacitor" C0603 21.59,105.41 r90 top value=4.7uF
C45 "Capacitor" C0402 16.51,103.632 r90 top value=100nF
C46 "Capacitor" C0402 16.764,99.568 r0 top value=10nF
C47 "Capacitor" C0402 13.97,98.044 r90 top value=1uF
C48 "Capacitor" C0402 13.97,96.266 r270 top value=1uF
C49 "Capacitor" C0603 13.716,92.075 r270 top value=4.7uF
C50 "Capacitor" C0603 18.796,92.075 r90 top value=4.7uF
C51 "Capacitor" C0402 13.716,89.535 r90 top value=100nF
C52 "Capacitor" C0603 13.716,84.709 r90 top value=4.7uF
C53 "Capacitor" C0603 18.796,84.709 r90 top value=4.7uF
C54 "Capacitor" C0402 15.748,81.661 r0 top value=100nF
C55 "Capacitor" C0402 88.9,78.994 r180 top value=100nF
C56 "Capacitor" C0402 133.338,70.751 r180 top value=100nF
C57 "Capacitor" C0402 13.95,69.4 r270 top value=100nF
C58 "Capacitor" C0402 130.048,68.326 r270 top value=100nF
C59 "Capacitor" C0402 135.128,67.818 r0 top value=100nF
C60 "Capacitor" C0603 127,67.056 r270 top value=1uF
C61 "Capacitor" C0603 128.27,67.056 r270 top value=1uF
C62 "Capacitor" C0402 130.048,66.548 r90 top value=100nF
C63 "Capacitor" C0603 39.116,55.626 r270 top value=1uF
C64 "Capacitor" C0402 37.592,55.626 r90 top value=100nF
C65 "Capacitor" C0402 32.766,53.086 r270 top value=10nF
C66 "Capacitor" C0603 37.592,52.578 r270 top value=100nF
C67 "Capacitor" C0603 39.116,52.578 r270 top value=1uF
C68 "Capacitor" C0402 28.702,49.022 r270 top value=100nF
C69 "Capacitor" C0402 32.766,49.022 r90 top value=100nF
C70 "Capacitor" C0603 7.62,44.45 r270 top value=1uF
C71 "Capacitor" C0402 14.224,44.196 r270 top value=100nF
C72 "Capacitor" C0603 6.8,42.1 r0 top value=4.7uF
C73 "Capacitor" C0402 121.92,41.656 r0 top value=100nF
C74 "Capacitor" C0402 6.6,39.5 r0 top value=100pF
C75 "Capacitor" C0805 137.65,45.15 r0 top value=10uF
C76 "Capacitor" C0402 138.25,43.775 r180 top value=100nF
C77 "Capacitor" C0603 29.718,33.782 r90 top value=2.2uF
C78 "Capacitor" C0402 126.492,28.956 r180 top value=100nF
C79 "Capacitor" C0402 138.25,42.525 r0 top value=100nF
C80 "Capacitor" C0402 119.634,13.97 r180 top value=10nF
C81 "Capacitor" C0402 121.92,13.97 r0 top value=10nF
C82 "Capacitor" C0402 124.206,13.97 r180 top value=10nF
C83 "Capacitor" C0402 126.492,13.97 r0 top value=10nF
C84 "Capacitor" C0402 128.778,13.97 r180 top value=10nF
C85 "Capacitor" C0603 141.986,13.081 r0 top value=4.7uF
C86 "Capacitor" C0402 8.128,168.148 r180 bottom value=4.7uF
C87 "Capacitor" C0402 1.778,165.1 r270 bottom value=100nF
C88 "Capacitor" C0603 8.636,163.83 r90 bottom value=1uF
C89 "Capacitor" C0603 39.243,163.068 r270 bottom value=1uF
C90 "Capacitor" C0402 1.778,163.068 r90 bottom value=1uF
C91 "Capacitor" C0402 40.386,162.814 r270 bottom value=100nF
C92 "Capacitor" C0402 31.96,160.655 r270 bottom value=1uF
C93 "Capacitor" C0402 3.302,160.274 r0 bottom value=1uF
C94 "Capacitor" C0805 13.335,156.21 r90 bottom value=4.7uF
C95 "Capacitor" C0402 11.938,156.718 r90 bottom value=100nF
C96 "Capacitor" C0603 40,153.2 r270 bottom value=100nF
C97 "Capacitor" C0402 124.968,149.225 r0 bottom value=100nF
C98 "Capacitor" C0402 80.01,147.828 r90 bottom value=100nF
C99 "Capacitor" C0402 82.042,147.066 r0 bottom value=100nF
C100 "Capacitor" C0805 146.812,145.542 r270 bottom value=4.7uF
C101 "Capacitor" C0402 148.336,145.288 r270 bottom value=100nF
C102 "Capacitor" C0603 72.136,143.51 r270 bottom value=4.7uF
C103 "Capacitor" C0603 51.562,143.51 r90 bottom value=3.6nF
C104 "Capacitor" C0402 70.866,143.51 r90 bottom value=100nF
C105 "Capacitor" C0603 12.192,141.224 r270 bottom value=2.2uF
C106 "Capacitor" C0603 51.562,140.97 r90 bottom value=3.6nF
C107 "Capacitor" C0402 82.296,140.97 r270 bottom value=100nF
C108 "Capacitor" C0402 81.28,140.97 r270 bottom value=100nF
C109 "Capacitor" C0402 80.264,140.97 r270 bottom value=1uF
C110 "Capacitor" C0402 13.335,140.97 r90 bottom value=100nF
C111 "Capacitor" C0402 13.208,138.684 r270 bottom value=100nF
C112 "Capacitor" C0402 77.724,138.176 r270 bottom value=100nF
C113 "Capacitor" C0402 76.708,138.176 r270 bottom value=100nF
C114 "Capacitor" C0402 161.798,137.668 r270 bottom value=100nF
C115 "Capacitor" C0402 160.528,137.668 r270 bottom value=100nF
C116 "Capacitor" C0402 70.358,137.922 r180 bottom value=100nF
C117 "Capacitor" C0402 16.51,137.414 r0 bottom value=100nF
C118 "Capacitor" C0402 77.724,136.144 r270 bottom value=1uF
C119 "Capacitor" C0402 76.708,136.144 r90 bottom value=100nF
C120 "Capacitor" C0402 80.01,134.874 r180 bottom value=100nF
C121 "Capacitor" C0402 80.01,133.985 r180 bottom value=100nF
C122 "Capacitor" C0402 88.646,133.858 r180 bottom value=100nF
C123 "Capacitor" C0402 86.995,133.858 r0 bottom value=100nF
C124 "Capacitor" C0402 78.105,131.445 r270 bottom value=100nF
C125 "Capacitor" C0402 83.693,130.048 r180 bottom value=100nF
C126 "Capacitor" C0402 85.598,128.778 r270 bottom value=100nF
C127 "Capacitor" C0402 84.709,128.778 r270 bottom value=100nF
C128 "Capacitor" C0402 83.058,123.063 r90 bottom value=100nF
C129 "Capacitor" C0402 82.042,123.063 r90 bottom value=100nF
C130 "Capacitor" C0402 85.09,119.38 r180 bottom value=100nF
C131 "Capacitor" C0402 37.846,104.902 r90 bottom value=100nF
C132 "Capacitor" C0402 33.02,102.362 r90 bottom value=100nF
C133 "Capacitor" C0603 81.28,101.6 r0 bottom value=4.7uF
C134 "Capacitor" C0402 79.248,101.6 r180 bottom value=100nF
C135 "Capacitor" C0402 36.322,98.044 r0 bottom value=100nF
C136 "Capacitor" C0402 81.167,96.083 r270 bottom value=100nF
C137 "Capacitor" C0402 85.09,92.456 r270 bottom value=100nF
C138 "Capacitor" C0402 86.614,78.232 r180 bottom value=100nF
C139 "Capacitor" C0402 84.836,78.232 r0 bottom value=100nF
C140 "Capacitor" C0402 92.202,77.978 r0 bottom value=100nF
C141 "Capacitor" C0402 89.916,77.978 r0 bottom value=100nF
C142 "Capacitor" C0603 64.262,77.216 r270 bottom value=4.7uF
C143 "Capacitor" C0402 94.488,77.47 r180 bottom value=100nF
C144 "Capacitor" C0603 84.582,73.914 r270 bottom value=4.7uF
C145 "Capacitor" C0402 94.488,73.66 r90 bottom value=100nF
C146 "Capacitor" C0402 93.472,73.66 r90 bottom value=100nF
C147 "Capacitor" C0603 135.128,73.152 r270 bottom value=1uF
C148 "Capacitor" C0603 133.604,73.152 r270 bottom value=1uF
C149 "Capacitor" C0402 86.36,72.898 r90 bottom value=100nF
C150 "Capacitor" C0402 91.186,70.612 r0 bottom value=100nF
C151 "Capacitor" C0603 137.922,70.358 r180 bottom value=22nF
C152 "Capacitor" C0402 94.361,70.485 r0 bottom value=100nF
C153 "Capacitor" C0402 64.008,70.358 r180 bottom value=100nF
C154 "Capacitor" C0402 85.852,69.596 r0 bottom value=100nF
C155 "Capacitor" C0402 84.074,69.596 r180 bottom value=100nF
C156 "Capacitor" C0402 66.294,69.596 r180 bottom value=100nF
C157 "Cap_POL_TANA" CPOL_TAJ-C_2312_H2P6 3.3,61.6 r270 bottom value="220uF 10V"
C158 "Capacitor" C0402 91.948,69.342 r180 bottom value=100nF
C159 "Capacitor" C0603 137.922,68.834 r180 bottom value=22nF
C160 "Capacitor" C0603 137.922,67.31 r180 bottom value=1uF
C161 "Capacitor" C0603 137.922,65.786 r180 bottom value=1uF
C162 "Capacitor" C0402 127.762,65.024 r180 bottom value=1.8nF
C163 "Capacitor" C0603 137.922,64.262 r180 bottom value=10uF
C164 "Capacitor" C0603 135.382,63.5 r90 bottom value=1uF
C165 "Capacitor" C0603 132.588,63.5 r270 bottom value=150pF
C166 "Capacitor" C0603 131.318,63.5 r270 bottom value=150pF
C167 "Capacitor" C0402 133.858,63.5 r90 bottom value=100nF
C168 "Capacitor" C0402 130.048,63.5 r90 bottom value=1.8nF
C169 "Capacitor" C0402 129.032,63.5 r90 bottom value=1uF
C170 "Capacitor" C0402 128.016,63.5 r90 bottom value=1uF
C171 "Capacitor" C0402 25.654,47.498 r180 bottom value=100nF
C172 "Capacitor" C0402 33.274,45.974 r90 bottom value=100nF
C173 "Capacitor" C0402 31.75,45.974 r270 bottom value=100nF
C174 "Capacitor" C0402 29.972,45.974 r270 bottom value=100nF
C175 "Capacitor" C0402 25.654,46.228 r180 bottom value=100nF
C176 "Capacitor" C0402 32.893,44.704 r0 bottom value=100nF
C177 "Capacitor" C0603 30.48,44.323 r180 bottom value=4.7uF
C178 "Capacitor" C0402 27.686,44.196 r0 bottom value=100nF
C179 "Capacitor" C0603 34.798,42.926 r180 bottom value=1uF
C180 "Capacitor" C0402 32.766,42.926 r0 bottom value=100nF
C181 "Capacitor" C0402 26.416,42.164 r180 bottom value=100nF
C182 "Capacitor" C0402 34.29,41.656 r180 bottom value=100nF
C183 "Capacitor" C0402 26.416,41.021 r180 bottom value=100nF
C184 "Capacitor" C0402 32.766,40.894 r0 bottom value=100nF
C185 "Capacitor" C0402 24.892,40.132 r0 bottom value=100nF
C186 "Capacitor" C0402 29.45,39.65 r180 bottom value=100nF
C187 "Capacitor" C0603 32.512,37.084 r90 bottom value=2.2uF
C188 "Capacitor" C0603 26.67,37.084 r90 bottom value=2.2uF
C189 "Capacitor" C0402 128.524,37.846 r90 bottom value=100nF
C190 "Capacitor" C0402 30.48,37.846 r90 bottom value=100nF
C191 "Capacitor" C0402 29.337,37.846 r90 bottom value=100nF
C192 "Capacitor" C0402 28.321,37.846 r90 bottom value=100nF
C193 "Capacitor" C0402 119.888,32.766 r270 bottom value=100nF
C194 "Capacitor" C0402 125.591,31.595 r0 bottom value=100nF
C195 "Capacitor" C0402 122.936,31.496 r180 bottom value=100nF
C196 "Capacitor" C0402 151.892,20.574 r180 bottom value=100nF
C197 "Capacitor" C0402 150.495,17.018 r180 bottom value=100nF
C198 "Capacitor" C0402 106.865,10.923 r180 bottom value=100nF
C199 "Capacitor" C0402 17.018,7.62 r270 bottom value=100nF
C200 "Capacitor" C0402 93.908,24.927 r180 top value=10pF
C201 "Capacitor" C0402 93.908,26.327 r180 top value=10pF
CART-1 "Comment" Sheetbox_6L2S 40,-25.6 r0 top
CN1 "Header 17x2 IDC34 MotorControl" CON_SAMTEC_TST-117-01-T-D 94.234,166.37 r180 top
CN2 "Socket 20x2 CLM_Reverse_for_camera" CON_SAMTEC_CLM-120-02-L-D_Reverse-to-Camera 162.555,147.185 r0 top locked value=CLM-120-02-L-D
CN3 "microSD-PJS008-2003" CON_MICROSD_YAMAICHI_PJS008-2003-1 0,158.115 r180 top locked value=PJS008-2003-1
CN4 "Socket 10x2" CON_FCI_20021311-XXX20XXLF 55.245,165.735 r180 top value=20021311-00020T4LF
CN5 "Header 30x2" CON_SAMTEC_FTR-130-53-L-D-LC 118.422,133.35 r270 top locked
CN6 "Header 30x2" CON_SAMTEC_FTR-130-53-L-D-LC 49.843,133.35 r270 top locked
CN7 "Jumper_Header 2x1" CON_SAMTEC_TSW-102-07-G-S 32.004,148.082 r0 top value="Shunt not fitted"
CN8 "USB_uAB_47590.0001" CON_USBMICROAB_MOLEX_47590-0001_H3 0.005,140.97 r270 top value="USB uAB ZX62RD-AB-5P8(30)"
CN9 "DB9_Header_male_2301843-2" CON_DB9-MALE_TYCO_2301843-2 2.54,116.84 r270 top value=DB9_Male_2301843-2
CN10 "Socket 10x2" CON_SAMTEC_ERF8-010-050-S-DV-TR 138,113.7 r270 top value=ERF8-010-05.0-S-DV-TR
CN11 "Socket 10x2" CON_SAMTEC_ERF8-010-050-S-DV-TR 164,113.7 r270 top value=ERF8-010-05.0-S-DV-TR
CN12 "Header 20x2" CON_SAMTEC_FTR-120-53-L-D-LC 59.823,100.33 r270 top locked
CN13 "Header 20x2" CON_SAMTEC_FTR-120-53-L-D-LC 108.442,100.33 r270 top locked
CN14 "Header 10x2" CON_CVILUX_CH87-20-2-V-1-00 164.465,82.585 r270 top value=TST-110-01-G-D
CN15 "Header 10x2" CON_SAMTEC_FTSH-110-01-L-DV 152.573,89.4 r90 top
CN16 "Header 7x2" CON_STDC14_Receiver_MEDIUM_WITH_MIPI10_3D 152.468,74.31 r90 top value="MIPI10 on STDC14 footprint"
CN17 "Power_Jack_DC10B" CON_DC-POWER-SOCKET_CLIFF_FC68149_DC10B 0,61.722 r180 top value=DC10B
CN18 "Jack_PJ3028B-3_4P" CON_PHONE-JACK-3P5_HY_PJ3028B 169.005,59.495 r180 top value=PJ3028B-3_4P
CN19 "Header 2x1" CON_SAMTEC_TSW-102-07-G-S 26.67,50.8 r90 top
CN20 "Jack_PJ3028B-3_4P" CON_PHONE-JACK-3P5_HY_PJ3028B 169,46.63 r180 top value=PJ3028B-3_4P
CN21 "USB_uB_105017.0001" CON_USBMICROB_MOLEX_105017-0001_H2P90 0,37.3 r270 top value=USB_uB_105017-0001
CN22 "DB9_Header_male_2301843-2" CON_DB9-MALE_TYCO_2301843-2 166.925,23.556 r90 top value=DB9_Male_2301843-2
CN23 "FH52E-40S-0.5SH" CON_HRS_FH52E-40S-05SH 83,30 r180 top locked value=FH52E-40S-05SH
CN24 "Socket 4x2" CON_SAMTEC_SSM-104-L-DH 7.308,22.355 r270 top value=SSM-104-L-DH
CN25 "Header 4x1" CON_SAMTEC_TSW-104-07-G-S 29.125,12.787 r0 top
CN26 "Header 4x1" CON_SAMTEC_TSW-104-07-G-S 107.95,12.7 r0 top
CN27 "USB_uAB_47590.0001" CON_USBMICROAB_MOLEX_47590-0001_H3 150.055,0.105 r0 top value="USB uAB ZX62RD-AB-5P8(30)"
CN28 "microSD-PJS008-2003" CON_MICROSD_YAMAICHI_PJS008-2003-1 168.901,147.352 r0 bottom locked value=PJS008-2003-1
CN29 "BATTERY HOLDER" BAT_HARWIN_S8411-45R_SMD_2P 32.766,59.944 r0 bottom value="CR1220 holder"
CN30 "Header 5x2 Generic" CON_SAMTEC_FTSH-105-01-L-DV-K 142.83,45.06 r90 top locked value=FTSH-105-01-L-DV-K
D1 "BAT60JFILM" DIO_SOD323 24.638,116.332 r270 top
D2 "BAT60JFILM" DIO_SOD323 17.018,109.474 r180 top
D3 "BAT60JFILM" DIO_SOD323 75.692,9.652 r180 top
D4 "BAT60JFILM" DIO_SOD323 11.574,76.25 r270 bottom
D5 "BAT60JFILM" DIO_SOD323 14.114,76.25 r270 bottom
D6 "BAT60JFILM" DIO_SOD323 16.654,76.25 r270 bottom
D7 "BAT60JFILM" DIO_SOD323 19.194,76.25 r270 bottom
D8 "BAT60JFILM" DIO_SOD323 21.734,76.25 r270 bottom
H1 "POSITION HOLE" PTH_M1261-3005-N_3P5X6_M3_H14 26.258,131.352 r0 top locked
H2 "POSITION HOLE" PTH_M1261-3005-N_3P5X6_M3_H14 142.742,131.352 r0 top locked
H3 "POSITION HOLE" PTH_M1261-3005-N_3P5X6_M3_H14 26.258,78.349 r0 top locked
H4 "POSITION HOLE" PTH_M1261-3005-N_3P5X6_M3_H14 142.742,78.349 r0 top locked
H5 "POSITION HOLE" PTH_M1261-3005-N_3P5X6_M3_H14 26.258,23.352 r0 top locked
H6 "POSITION HOLE" PTH_M1261-3005-N_3P5X6_M3_H14 142.742,23.352 r0 top locked
H7 "POSITION HOLE" PTH_M1261-3005-N_3P5X6_M3_H14 136.332,166.65 r180 bottom
H8 "POSITION HOLE" PTH_M1261-3005-N_3P5X6_M3_H14 33.462,166.65 r180 bottom locked
H9 "POSITION HOLE" PTH_M1261-3005-N_3P5X6_M3_H14 136.332,5.36 r180 bottom
H10 "POSITION HOLE" PTH_M1261-3005-N_3P5X6_M3_H14 33.462,5.36 r180 bottom locked
HW21 "STICKER_BOARD_CPN" STICKER_25X9 111.3,22.3 r0 top value="Board CPN"
HW23 "STICKER_BOARD_REF" STICKER_25X9 80.775,46.6 r180 bottom value="MBxxxxy-zz syywwxxxxx"
JP1 "Jumper_Header 3x1 Fitted 1-2" CON_SAMTEC_TSW-103-07-F-S 26.7,160.7 r270 top value="Shunt Fitted 1-2"
JP2 "Jumper_Header 3x1" CON_SAMTEC_TSW-103-07-F-S 33.02,152.146 r0 top value="Header 3x1"
JP3 "Jumper_Header 2x1 Fitted" CON_SAMTEC_TSW-102-07-G-S 68.072,150.368 r0 top value="Shunt Fitted"
JP4 "Jumper_Header 3x1 Fitted 1-2" CON_SAMTEC_TSW-103-07-F-S 33.275,134.875 r180 top value="Shunt Fitted 1-2"
JP5 "Jumper_Header 2x1" CON_SAMTEC_TSW-102-07-G-S 37.592,148.082 r0 top value="Shunt not fitted"
JP6 "Jumper_Header 3x1 Fitted 1-2" CON_SAMTEC_TSW-103-07-F-S 138.43,146.304 r180 top value="Shunt Fitted 1-2"
JP7 "Jumper_Header 3x1 Fitted 1-2" CON_SAMTEC_TSW-103-07-F-S 33.274,144.78 r0 top value="Shunt Fitted 1-2"
JP8 "Jumper_Header 3x1 Fitted 1-2" CON_SAMTEC_TSW-103-07-F-S 138.43,143.51 r0 top value="Shunt Fitted 1-2"
JP9 "Jumper_Header 3x1 Fitted 1-2" CON_SAMTEC_TSW-103-07-F-S 33.274,141.478 r0 top value="Shunt Fitted 1-2"
JP10 "Jumper_Header 2x1" CON_SAMTEC_TSW-102-07-G-S 38.862,140.208 r270 top value="Shunt not fitted"
JP11 "Jumper_Header 3x1 Fitted 1-2" CON_SAMTEC_TSW-103-07-F-S 33.274,138.176 r0 top value="Shunt Fitted 1-2"
JP12 "Jumper_Header 3x1 Fitted 1-2" CON_SAMTEC_TSW-103-07-F-S 138.43,135.89 r180 top value="Shunt Fitted 1-2"
JP13 "Jumper_Header 2x1" CON_SAMTEC_TSW-102-07-G-S 32.766,129.54 r270 top value="Shunt not fitted"
JP14 "Jumper_Header 2x1" CON_SAMTEC_TSW-102-07-G-S 135.89,131.318 r270 top value="Shunt not fitted"
JP15 "Jumper_Header 2x1 Fitted" CON_SAMTEC_TSW-102-07-G-S 137.16,149.098 r0 top value="Shunt Fitted"
JP16 "Jumper_Header 2x1" CON_SAMTEC_TSW-102-07-G-S 35.814,129.54 r270 top value="Shunt not fitted"
JP17 "Jumper_Header 3x1 Fitted 1-2" CON_SAMTEC_TSW-103-07-F-S 33.274,124.968 r180 top value="Shunt Fitted 1-2"
JP18 "Jumper_Header 2x1 Fitted" CON_SAMTEC_TSW-102-07-G-S 27.432,122.936 r270 top value="Shunt Fitted"
JP19 "Jumper_Header 3x1 Fitted 1-2" CON_SAMTEC_TSW-103-07-F-S 33.274,121.666 r180 top value="Shunt Fitted 1-2"
JP20 "Jumper_Header 2x1 Fitted" CON_SAMTEC_TSW-102-07-G-S 28.702,118.364 r0 top value="Shunt Fitted"
JP21 "Jumper_Header 2x1 Fitted" CON_SAMTEC_TSW-102-07-G-S 34.544,118.364 r0 top value="Shunt Fitted"
JP22 "Jumper_Header 2x1" CON_SAMTEC_TSW-102-07-G-S 33.275,108.468 r0 top value="Shunt not fitted"
JP23 "Jumper_Header 3x1 Fitted 1-2" CON_SAMTEC_TSW-103-07-F-S 33.235,111.8 r180 top value="Shunt Fitted 1-2"
JP24 "Jumper_Header 2x1" CON_SAMTEC_TSW-102-07-G-S 17.272,112.014 r0 top value="Shunt not fitted"
JP25 "Jumper_Header 2x1" CON_SAMTEC_TSW-102-07-G-S 84.582,107.95 r0 top value="Shunt not fitted"
JP26 "Jumper_Header 2x1" CON_SAMTEC_TSW-102-07-G-S 134.747,97.282 r270 top value="Shunt not fitted"
JP27 "Jumper_Header 2x1" CON_SAMTEC_TSW-102-07-G-S 137.795,97.282 r270 top value="Shunt not fitted"
JP28 "Jumper_Header 2x1" CON_SAMTEC_TSW-102-07-G-S 140.97,97.282 r270 top value="Shunt not fitted"
JP29 "Jumper_Header 6x2 Fitted 3-4" CON_SAMTEC_TSW-106-07-X-D 7.62,90.297 r270 top value="Shunt Fitted 3-4"
JP30 "Jumper_Header 2x1" CON_SAMTEC_TSW-102-07-G-S 45.72,94.234 r90 top value="Shunt not fitted"
JP31 "Jumper_Header 2x1" CON_SAMTEC_TSW-102-07-G-S 49.022,94.234 r90 top value="Shunt not fitted"
JP32 "Jumper_Header 3x1 Fitted 1-2" CON_SAMTEC_TSW-103-07-F-S 86,112.2 r180 top value="Shunt Fitted 1-2"
JP34 "Jumper_Header 2x1" CON_SAMTEC_TSW-102-07-G-S 140.97,91.186 r270 top value="Shunt not fitted"
JP35 "Jumper_Header 3x1 Fitted 2-3" CON_SAMTEC_TSW-103-07-F-S 134.747,89.916 r270 top value="Shunt Fitted 2-3"
JP37 "Jumper_Header 3x1 Fitted 1-2" CON_SAMTEC_TSW-103-07-F-S 43.942,50.038 r0 top value="Shunt Fitted 1-2"
JP38 "Jumper_Header 2x1" CON_SAMTEC_TSW-102-07-G-S 151.892,25.4 r270 top value="Shunt not fitted"
JP39 "Jumper_Header 2x1" CON_SAMTEC_TSW-102-07-G-S 28.702,115.062 r0 top value="Shunt not fitted"
JP40 "Jumper_Header 2x1" CON_SAMTEC_TSW-102-07-G-S 34.544,115.062 r0 top value="Shunt not fitted"
JPME1 "Jumper_Header 3x1" CON_SAMTEC_TSW-103-07-F-S 6.985,170.18 r180 top value="Header 3x1"
L1 "Inductor" L0805_H0P9 86.106,145.796 r90 top value="2.2uH, 1.2A"
L2 "BNX002-01" FIL_MURATA_BNX002-01 6.39,73.747 r270 top
LD1 "LED_green" LED_0603_OSRAM_LG-Q396-PS-35_GREEN_1A2K_H0P4 85.36,14.332 r90 top value=GREEN
LD2 "LED_red" LED_0603_VISHAY_VLMS1300-GS08_RED_1A2K_H0P8 89.17,14.332 r90 top value=RED
LD3 "LED_yellow" LED_0603_OSRAM_LY-Q396-P1Q2-36_YELLOW_1A2K_H0P4 92.98,14.332 r90 top value=YELLOW
LD4 "LED_orange" LED_0603_OSRAM_LO-Q976-PS-25_ORANGE_1A2K_H0P8 96.79,14.332 r90 top value=ORANGE
LD5 "LED_red" LED_0603_VISHAY_VLMS1300-GS08_RED_1A2K_H0P8 4.115,135.165 r0 top value=RED
LD6 "LED_green" LED_0603_OSRAM_LG-Q396-PS-35_GREEN_1A2K_H0P4 4.115,133.665 r0 top value=GREEN
LD7 "LED_green" LED_0603_OSRAM_LG-Q396-PS-35_GREEN_1A2K_H0P4 1.905,99.314 r180 top value=GREEN
LD8 "LED_red" LED_0603_VISHAY_VLMS1300-GS08_RED_1A2K_H0P8 2,47.5 r0 top value=RED
LD9 "LD_BICOLOR_CMS" LED_BI-GR_HSMF-A201-A00J1 2.877,11.278 r270 top
LD10 "LED_red" LED_0603_VISHAY_VLMS1300-GS08_RED_1A2K_H0P8 141.697,4.705 r90 top value=RED
LD11 "LED_green" LED_0603_OSRAM_LG-Q396-PS-35_GREEN_1A2K_H0P4 143.297,4.705 r90 top value=GREEN
MIRE-PLACE-3 "MIRE-PLACE-3" MIRE_PLACE_SMD_0P8MM 157,170 r0 top
MIRE-PLACE-4 "MIRE-PLACE-3" MIRE_PLACE_SMD_0P8MM 3,3 r0 top
MIRE-PLACE-5 "MIRE-PLACE-3" MIRE_PLACE_SMD_0P8MM 160,5 r0 top
MIRE-PLACE-6 "MIRE-PLACE-3" MIRE_PLACE_SMD_0P8MM 157,170 r180 bottom
MIRE-PLACE-7 "MIRE-PLACE-3" MIRE_PLACE_SMD_0P8MM 160,5 r180 bottom
MIRE-PLACE-8 "MIRE-PLACE-3" MIRE_PLACE_SMD_0P8MM 3,3 r180 bottom
Q1 "BSN20" MOS_SOT23 149.098,155.702 r180 bottom value=BSN20BK
Q2 "BSN20" MOS_SOT23 144.018,155.702 r180 bottom value=BSN20BK
R1 "Resistor" R0603 121.92,169.926 r270 top value=150R
R2 "Resistor" R0603 121.92,167.386 r90 top value=120R
R3 "Resistor" R0402 24,166.9 r180 top value=10K
R4 "Resistor" R0603 18.034,165.1 r0 top value=0R
R5 "Resistor" R0603 21.59,163.322 r270 top value=0R
R6 "Resistor" R0603 18.034,163.576 r0 top value=0R
R7 "Resistor" R0603 100.584,159.766 r90 top value=100K
R8 "Resistor" R0402 80.01,160.02 r270 top value=3K3
R9 "Resistor" R0402 114.3,160.02 r270 top value=3K3
R10 "Resistor" R0402 21.082,159.766 r0 top value=47K
R11 "Resistor" R0402 21.082,158.496 r0 top value=47K
R12 "Resistor" R0402 21.082,157.226 r0 top value=10K
R13 "Resistor" R0402 21.082,153.924 r0 top value=47K
R14 "Resistor" R0402 21.082,152.908 r0 top value=47K
R15 "Resistor" R0402 136.398,151.13 r0 top value=10K
R16 "Resistor" R0402 124.968,149.225 r180 top value=0R
R17 "Resistor" R0603 16.256,147.574 r90 top value=0R
R18 "Resistor" R0603 17.78,147.574 r90 top value=0R
R19 "Resistor" R0603 19.304,147.574 r90 top value=0R
R20 "Resistor" R0402 76.962,147.32 r270 top value=0R
R21 "Resistor" R0402 77.978,147.32 r270 top value=0R
R22 "Resistor" R0603 81.788,146.558 r90 top value=0R
R23 "Resistor" R0402 91.5,146.55 r270 top value=0R
R24 "Resistor" R0402 92.6,146.55 r270 top value=0R
R25 "Resistor" R0603 16.256,145.288 r90 top value=0R
R26 "Resistor" R0603 17.78,145.288 r90 top value=0R
R27 "Resistor" R0603 19.304,145.288 r90 top value=0R
R28 "Resistor" R0402 13.462,144.272 r0 top value=10K
R29 "Resistor" R0402 112.014,144.145 r0 top value=0R
R30 "Resistor" R0402 96.266,143.764 r90 top value=10K
R31 "Resistor" R0402 97.536,143.764 r270 top value=10K
R32 "Resistor" R0603 124.968,142.875 r180 top value=47R
R33 "Resistor" R0402 43.942,141.605 r0 top value=0R
R34 "Resistor" R0402 124.968,137.795 r180 top value=0R
R35 "Resistor" R0603 43.942,136.398 r90 top value=0R
R36 "Resistor" R0603 10.668,136.652 r180 top value=820R
R37 "Resistor" R0603 11.684,134.62 r270 top value=8K06
R38 "Resistor" R0402 13.97,134.932 r90 top value=100R
R39 "Resistor" R0402 12.954,134.874 r90 top value=0R
R40 "Resistor" R0402 14.986,134.874 r90 top value=100K
R41 "Resistor" R0402 16.002,134.874 r270 top value=4K7
R42 "Resistor" R0402 1.615,135.165 r180 top value=360R
R43 "Resistor" R0402 43.942,134.366 r90 top value=1K
R44 "Resistor" R0805 7.112,134.112 r180 top value=0R_0805
R45 "Resistor" R0603 19.304,134.112 r180 top value=0R
R46 "Resistor" R0402 1.615,133.665 r180 top value=270R
R47 "Resistor" R0603 19.304,132.588 r180 top value=0R
R48 "Resistor" R0402 124.968,132.715 r0 top value=0R
R49 "Resistor" R0402 127.254,132.715 r0 top value=0R
R50 "Resistor" R0603 43.688,131.572 r0 top value=0R
R51 "Resistor" R0402 124.968,131.445 r180 top value=0R
R52 "Resistor" R0402 17.018,130.302 r90 top value=10K
R53 "Resistor" R0603 127.762,130.429 r180 top value=47R
R54 "Resistor" R0402 124.968,130.429 r180 top value=0R
R55 "Resistor" R0603 43.688,130.175 r0 top value=0R
R56 "Resistor" R0402 124.968,129.286 r180 top value=0R
R57 "Resistor" R0603 127.762,129.032 r180 top value=47R
R58 "Resistor" R0402 112.014,128.905 r0 top value=0R
R59 "Resistor" R0603 127.762,127.635 r180 top value=47R
R60 "Resistor" R0402 112.014,127.635 r0 top value=10K
R61 "Resistor" R0402 112.014,126.365 r0 top value=0R
R62 "Resistor" R0402 124.968,125.73 r180 top value=0R
R63 "Resistor" R0402 112.014,125.095 r0 top value=0R
R64 "Resistor" R0402 124.968,118.745 r180 top value=0R
R65 "Resistor" R0402 104.648,115.824 r270 top value=0R
R66 "Resistor" R0402 105.664,115.824 r270 top value=0R
R67 "Resistor" R0603 62.992,114.554 r0 top value=0R
R68 "Resistor" R0402 53.594,112.395 r0 top value=0R
R69 "Resistor" R0402 115.062,112.141 r180 top value=0R
R70 "Resistor" R0402 65.786,111.125 r0 top value=0R
R71 "Resistor" R0402 115.062,111.125 r180 top value=0R
R72 "Resistor" R0603 53.594,109.855 r0 top value=0R
R73 "Resistor" R0402 65.786,109.855 r180 top value=0R
R74 "Resistor" R0402 102.616,109.855 r180 top value=0R
R75 "Resistor" R0402 115.062,109.855 r180 top value=0R
R76 "Resistor" R0402 65.786,108.712 r180 top value=0R
R77 "Resistor" R0402 53.594,108.585 r0 top value=0R
R78 "Resistor" R0402 102.616,108.585 r180 top value=0R
R79 "Resistor" R0402 88.646,108.458 r180 top value=10K
R80 "Resistor" R0402 115.062,108.458 r180 top value=0R
R81 "Resistor" R0603 53.594,107.315 r0 top value=0R
R82 "Resistor" R0402 115.062,107.442 r180 top value=0R
R83 "Resistor" R0402 19.304,107.188 r180 top value=27K
R84 "Resistor" R0402 88.138,105.918 r90 top value=10K
R85 "Resistor" R0402 90.424,105.918 r270 top value=10K
R86 "Resistor" R0402 91.44,105.918 r270 top value=220K
R87 "Resistor" R0402 65.786,106.045 r0 top value=0R
R88 "Resistor" R0402 102.616,106.045 r180 top value=0R
R89 "Resistor" R0402 115.062,106.045 r180 top value=0R
R90 "Resistor" R0402 19.3,108.1 r180 top value=56K
R91 "Resistor" R0402 81.28,105.664 r0 top value=10K
R92 "Resistor" R0402 85.09,105.664 r0 top value=220K
R93 "Resistor" R0402 118.7,104.8 r180 top value=0R
R94 "Resistor" R0402 28.448,104.902 r0 top value=10K
R95 "Resistor" R0402 53.594,104.775 r0 top value=0R
R96 "Resistor" R0402 65.786,104.775 r0 top value=0R
R97 "Resistor" R0402 102.616,104.775 r180 top value=0R
R98 "Resistor" R0402 115.062,104.775 r180 top value=0R
R99 "Resistor" R0402 14.478,103.632 r270 top value=10K
R100 "Resistor" R0402 15.494,103.632 r90 top value=10K
R101 "Resistor" R0402 115.062,103.505 r180 top value=0R
R102 "Resistor" R0402 65.786,103.505 r0 top value=0R
R103 "Resistor" R0402 65.786,102.235 r0 top value=0R
R104 "Resistor" R0402 115.3,146.7 r180 bottom value=0R
R105 "Resistor" R0402 65.786,100.965 r0 top value=0R
R106 "Resistor" R0402 28.448,100.838 r180 top value=10K
R107 "Resistor" R0402 92.202,100.838 r180 top value=220K
R108 "Resistor" R0402 44,139.2 r0 top value=0R
R109 "Resistor" R0402 102.616,99.695 r180 top value=10K
R110 "Resistor" R0402 115.3,145.415 r0 bottom value=0R
R111 "Resistor" R0402 144.78,99.568 r180 top value=10K
R112 "Resistor" R0402 4.26,99.314 r180 top value=620R
R113 "Resistor" R0402 115.062,97.155 r180 top value=0R
R114 "Resistor" R0402 102.616,98.425 r180 top value=0R
R115 "Resistor" R0402 115.062,98.425 r180 top value=0R
R116 "Resistor" R0402 136.9,102.85 r270 bottom value=0R
R117 "Resistor" R0402 102.616,97.155 r180 top value=0R
R118 "Resistor" R0402 115.062,99.568 r180 top value=0R
R119 "Resistor" R0402 102.616,93.726 r180 top value=0R
R120 "Resistor" R0603 112.2,145.5 r0 bottom value=0R
R121 "Resistor" R0402 102.616,92.075 r0 top value=0R
R122 "Resistor" R0402 38.5,136.55 r0 bottom value=0R
R123 "Resistor" R0603 53.594,90.805 r0 top value=0R
R124 "Resistor" R0402 102.616,90.805 r0 top value=0R
R125 "Resistor" R0603 75.375,24.725 r0 top value=0R
R126 "Resistor" R0603 75.375,26.125 r0 top value=0R
R127 "Resistor" R0402 65.278,89.154 r270 top value=0R
R128 "Resistor" R0402 102.616,89.408 r180 top value=0R
R129 "Resistor" R0402 15.748,89.027 r0 top value=10K
R130 "Resistor" R0402 13.716,87.757 r90 top value=10K
R131 "Resistor" R0402 102.616,87.884 r0 top value=0R
R132 "Resistor" R0402 60.706,85.852 r90 top value=0R
R133 "Resistor" R0402 13.716,82.169 r90 top value=10K
R134 "Resistor" R0402 90.678,78.994 r180 top value=10K
R135 "Resistor" R0402 128.27,73.152 r90 top value=0R
R136 "Resistor" R0402 129.286,73.152 r90 top value=0R
R137 "Resistor" R0402 130.302,73.152 r90 top value=0R
R138 "Resistor" R0603 137.922,70.358 r180 top value=0R
R139 "Resistor" R0402 127.254,69.85 r180 top value=0R
R140 "Resistor" R0402 127.254,68.834 r180 top value=0R
R141 "Resistor" R0603 137.414,68.072 r90 top value=0R
R142 "Resistor" R0402 67.056,65.786 r270 top value=10K
R143 "Resistor" R0402 93.218,65.532 r0 top value=10K
R144 "Resistor" R0402 32.766,51.308 r90 top value=10K
R145 "Resistor" R0402 29.972,49.022 r270 top value=100R
R146 "Resistor" R0402 20.066,46.99 r180 top value=4K7
R147 "Resistor" R0402 22.098,46.99 r0 top value=4K7
R148 "Resistor" R0402 8.89,45.974 r90 top value=10K
R149 "Resistor" R0402 1.778,45.72 r270 top value=820R
R150 "Resistor" R0402 3.048,45.72 r270 top value=100K
R151 "Resistor" R0402 22.098,45.212 r180 top value=10K
R152 "Resistor" R0402 8.89,44.196 r270 top value=10K
R153 "Resistor" R0402 20.066,43.942 r180 top value=2K7
R154 "Resistor" R0402 22.098,43.942 r180 top value=4K7
R155 "Resistor" R0603 147.975,44.775 r90 top value=0R
R156 "Resistor" R0603 149.4,44.775 r90 top value=0R
R157 "Resistor" R0402 22.098,39.37 r180 top value=100R
R158 "Resistor" R0603 131.275,37.375 r90 top value=0R
R159 "Inductor" IND_0603_H0P8 137.8,46.725 r180 top value="600R @ 100MHz"
R161 "Resistor" R0402 117.348,36.957 r0 top value=0R
R162 "Resistor" R0402 117.348,35.941 r0 top value=0R
R163 "Resistor" R0402 117.348,34.925 r180 top value=510R
R164 "Resistor" R0402 27.178,33.782 r90 top value=100R
R165 "Resistor" R0402 28.448,33.782 r90 top value=3K
R166 "Resistor" R0402 117.348,33.909 r0 top value=10K
R167 "Resistor" R0402 117.348,32.893 r180 top value=10K
R168 "Resistor" R0603 117.348,31.623 r0 top value=0R
R169 "Resistor" R0603 154.94,29.718 r270 top value=0R
R170 "Resistor" R0603 123.952,28.956 r0 top value=0R
R171 "Resistor" R0402 121.666,28.956 r0 top value=47K
R172 "Resistor" R0402 124.206,27.686 r0 top value=100K
R173 "Resistor" R0402 126.492,27.686 r0 top value=10K
R174 "Resistor" R0603 154.94,26.924 r90 top value=0R
R175 "Resistor" R0402 148.59,23.622 r90 top value=10K
R176 "Resistor" R0402 149.86,23.622 r90 top value=120R
R177 "Resistor" R0402 16.129,19.558 r0 top value=0R
R178 "Resistor" R0402 85.344,17.018 r90 top value=270R
R179 "Resistor" R0402 89.154,17.018 r90 top value=360R
R180 "Resistor" R0402 92.964,17.018 r90 top value=470R
R181 "Resistor" R0402 96.774,17.018 r90 top value=300R
R182 "Resistor" R0805 141.732,14.605 r180 top value=0R_0805
R183 "Resistor" R0402 119.634,14.986 r0 top value=10K
R184 "Resistor" R0402 121.92,14.986 r180 top value=10K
